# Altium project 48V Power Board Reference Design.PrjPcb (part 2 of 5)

## Sheet TPS4HC120-Q1.SchDoc
size 431 x 279 mm; Date: Not shown in title block; ApprovedBy: Not shown in title block; CheckedBy: Not shown in title block; Author: Not shown in title block; CompanyName: Not shown in title block; Engineer: Not shown in title block; Organization: Not shown in title block; Address1: Not shown in title block; Address2: Not shown in title block; Address3: Not shown in title block; Address4: Not shown in title block; DocumentNumber: 12; Revision: Use project parameter SCH_Rev; SheetNumber: 9; SheetTotal: 15; PageSetup: Record=PageOptions¦CenterHorizontal=True¦CenterVertical=True¦PrintScale=1.00¦XCorrection=1.00¦YCorrection=1.00¦PrintKind=0¦BorderSize=5000000¦LeftOffset=0¦BottomOffset=0¦Orientation=2¦PaperLength=1000¦PaperWidth=1000¦Scale=100¦PaperSource=15¦PrintQuality=600¦MediaType=1¦DitherType=10¦PaperKind=Letter¦PrintScaleMode=1
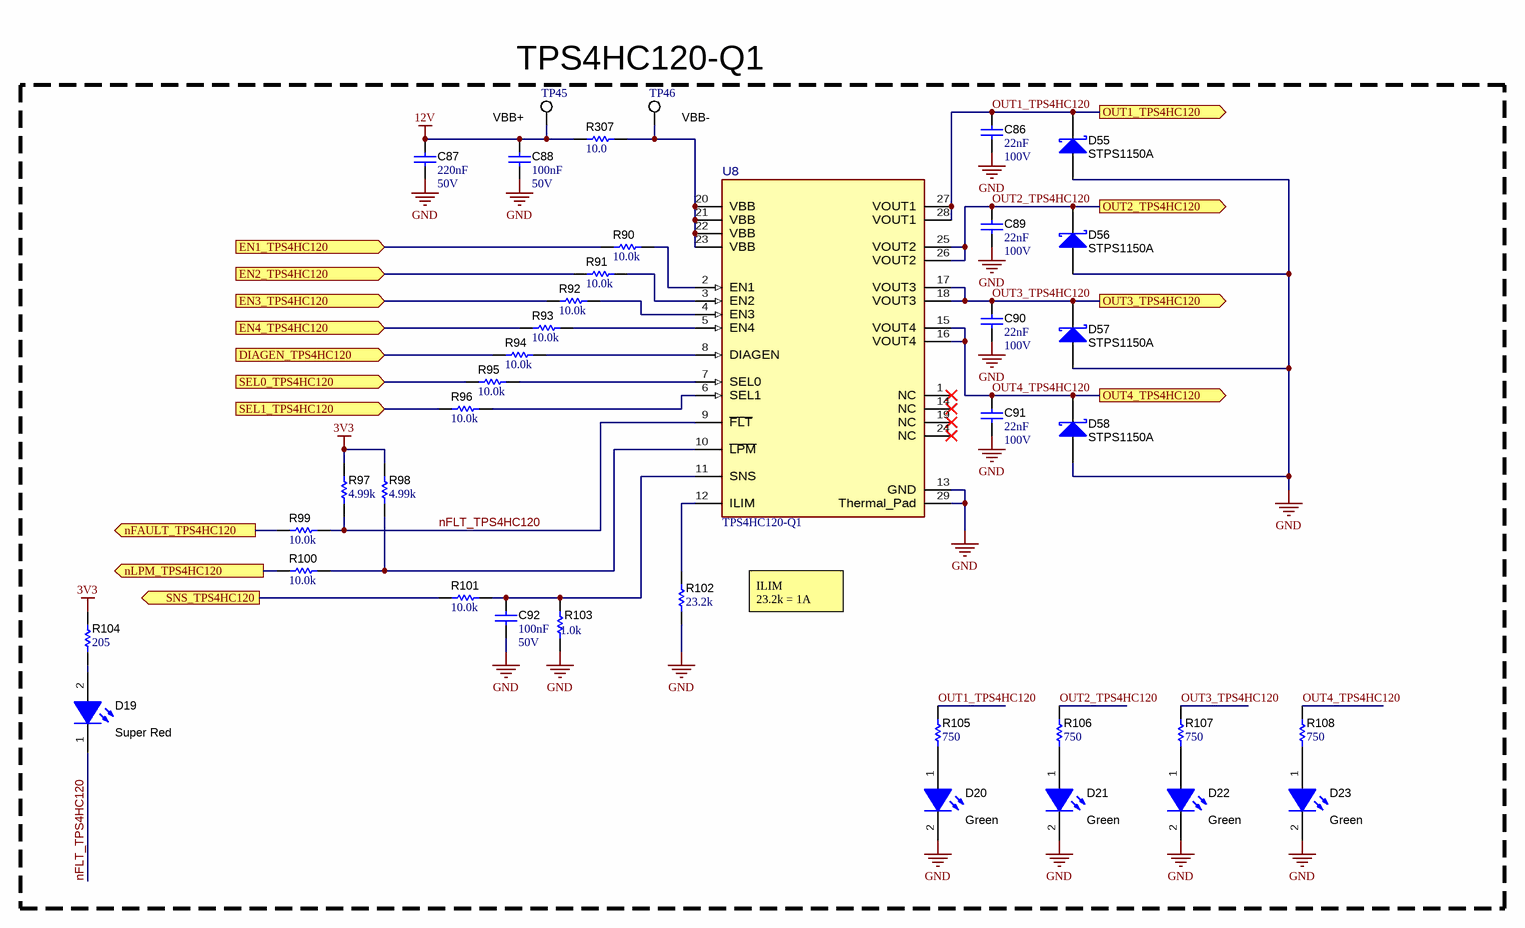
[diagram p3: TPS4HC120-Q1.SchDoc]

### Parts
C86  Cap_F: 22nF  VDC_V: 100V  [0603]  (hidden comment: CGA3E2X7R2A223K080AA)
C87  Cap_F: 220nF  VDC_V: 50V  [0603]  (hidden comment: GCJ188R71H224KA01D)
C88  Cap_F: 100nF  VDC_V: 50V  [0603]  (hidden comment: 06035C104KAZ2A)
C89  Cap_F: 22nF  VDC_V: 100V  [0603]  (hidden comment: CGA3E2X7R2A223K080AA)
C90  Cap_F: 22nF  VDC_V: 100V  [0603]  (hidden comment: CGA3E2X7R2A223K080AA)
C91  Cap_F: 22nF  VDC_V: 100V  [0603]  (hidden comment: CGA3E2X7R2A223K080AA)
C92  Cap_F: 100nF  VDC_V: 50V  [0603]  (hidden comment: 06035C104KAZ2A)
D19  value Super Red  [WL-SMCW_RED]  (hidden comment: 150060SS75000)
D20  value Green  [LTST-C191_Green]  (hidden comment: LTST-C191KGKT)
D21  value Green  [LTST-C191_Green]  (hidden comment: LTST-C191KGKT)
D22  value Green  [LTST-C191_Green]  (hidden comment: LTST-C191KGKT)
D23  value Green  [LTST-C191_Green]  (hidden comment: LTST-C191KGKT)
D55  STPS1150A  [SMA]
D56  STPS1150A  [SMA]
D57  STPS1150A  [SMA]
D58  STPS1150A  [SMA]
R90  ValueDisplayed: 10.0k  [0603]  (hidden comment: RMCF0603FT10K0)
R91  ValueDisplayed: 10.0k  [0603]  (hidden comment: RMCF0603FT10K0)
R92  ValueDisplayed: 10.0k  [0603]  (hidden comment: RMCF0603FT10K0)
R93  ValueDisplayed: 10.0k  [0603]  (hidden comment: RMCF0603FT10K0)
R94  ValueDisplayed: 10.0k  [0603]  (hidden comment: RMCF0603FT10K0)
R95  ValueDisplayed: 10.0k  [0603]  (hidden comment: RMCF0603FT10K0)
R96  ValueDisplayed: 10.0k  [0603]  (hidden comment: RMCF0603FT10K0)
R97  ValueDisplayed: 4.99k  [0603]  (hidden comment: CRCW06034K99FKEA)
R98  ValueDisplayed: 4.99k  [0603]  (hidden comment: CRCW06034K99FKEA)
R99  ValueDisplayed: 10.0k  [0603]  (hidden comment: RMCF0603FT10K0)
R100  ValueDisplayed: 10.0k  [0603]  (hidden comment: RMCF0603FT10K0)
R101  ValueDisplayed: 10.0k  [0603]  (hidden comment: RMCF0603FT10K0)
R102  ValueDisplayed: 23.2k  [0603]  (hidden comment: CRCW060323K2FKEA)
R103  ValueDisplayed: 1.0k  [0603]  (hidden comment: ESR03EZPJ102)
R104  ValueDisplayed: 205  [0603]  (hidden comment: RC0603FR-07205RL)
R105  ValueDisplayed: 750  [0603]  (hidden comment: RC0603FR-07750RL)
R106  ValueDisplayed: 750  [0603]  (hidden comment: RC0603FR-07750RL)
R107  ValueDisplayed: 750  [0603]  (hidden comment: RC0603FR-07750RL)
R108  ValueDisplayed: 750  [0603]  (hidden comment: RC0603FR-07750RL)
R307  ValueDisplayed: 10.0  [0603]  (hidden comment: RC0603FR-0710RL)
TP45  VBB+  [Keystone5012]
TP46  VBB-  [Keystone5012]
U8  TPS4HC120-Q1  [DGQ0028A-MFG]

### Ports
DIAGEN_TPS4HC120 (in), EN1_TPS4HC120 (in), EN2_TPS4HC120 (in), EN3_TPS4HC120 (in), EN4_TPS4HC120 (in), nFAULT_TPS4HC120 (out), nLPM_TPS4HC120 (out), OUT1_TPS4HC120 (out), OUT2_TPS4HC120 (out), OUT3_TPS4HC120 (out), OUT4_TPS4HC120 (out), SEL0_TPS4HC120 (in), SEL1_TPS4HC120 (in), SNS_TPS4HC120 (out)

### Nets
3V3: R97.2 R98.2 R104.2
12V: C87.1 C88.1 R307.1 TP45.1
GND: C86.2 C87.2 C88.2 C89.2 C90.2 C91.2 C92.2 D20.2(K) D21.2(K) D22.2(K) D23.2(K) D55.2(A) D56.2(A) D57.2(A) D58.2(A) R102.1 R103.1 U8.13(GND) U8.29(Thermal_Pad)
DIAGEN_TPS4HC120: R94.2 ; port DIAGEN_TPS4HC120
EN1_TPS4HC120: R90.2 ; port EN1_TPS4HC120
EN2_TPS4HC120: R91.2 ; port EN2_TPS4HC120
EN3_TPS4HC120: R92.2 ; port EN3_TPS4HC120
EN4_TPS4HC120: R93.2 ; port EN4_TPS4HC120
nFAULT_TPS4HC120: R99.2 ; port nFAULT_TPS4HC120
nFLT_TPS4HC120: D19.1(K) R97.1 R99.1 U8.9(~{FLT})  [project net nFLT_TPS4HC120_9]
nLPM_TPS4HC120: R100.2 ; port nLPM_TPS4HC120
OUT1_TPS4HC120: C86.1 D55.1(K) R105.2 U8.27(VOUT1) U8.28(VOUT1) ; port OUT1_TPS4HC120
OUT2_TPS4HC120: C89.1 D56.1(K) R106.2 U8.25(VOUT2) U8.26(VOUT2) ; port OUT2_TPS4HC120
OUT3_TPS4HC120: C90.1 D57.1(K) R107.2 U8.17(VOUT3) U8.18(VOUT3) ; port OUT3_TPS4HC120
OUT4_TPS4HC120: C91.1 D58.1(K) R108.2 U8.15(VOUT4) U8.16(VOUT4) ; port OUT4_TPS4HC120
SEL0_TPS4HC120: R95.2 ; port SEL0_TPS4HC120
SEL1_TPS4HC120: R96.2 ; port SEL1_TPS4HC120
SNS_TPS4HC120: R101.2 ; port SNS_TPS4HC120
NetC92_1: C92.1 R101.1 R103.2 U8.11(SNS)
NetD19_2: D19.2(A) R104.1
NetD20_1: D20.1(A) R105.1
NetD21_1: D21.1(A) R106.1
NetD22_1: D22.1(A) R107.1
NetD23_1: D23.1(A) R108.1
NetR90_1: R90.1 U8.2(EN1)
NetR91_1: R91.1 U8.3(EN2)
NetR92_1: R92.1 U8.4(EN3)
NetR93_1: R93.1 U8.5(EN4)
NetR94_1: R94.1 U8.8(DIAGEN)
NetR95_1: R95.1 U8.7(SEL0)
NetR96_1: R96.1 U8.6(SEL1)
NetR98_1: R98.1 R100.1 U8.10(~{LPM})
NetR102_2: R102.2 U8.12(ILIM)
NetR307_2: R307.2 TP46.1 U8.20(VBB) U8.21(VBB) U8.22(VBB) U8.23(VBB)

Not connected (* = marked no-connect by the designer): U8 1(NC)* 14(NC)* 19(NC)* 24(NC)*

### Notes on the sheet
- TPS4HC120-Q1
- ILIM                      23.2k = 1A

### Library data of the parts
C86 C89-C91 = CMP-0007086-4: CAP, CERM, 0.022 uF, 100 V, +/- 10%, X7R, AEC-Q200 Grade 1, 0603; Manufacturer: TDK; TaMin_C: -55°C; ESR_ohm: 83.542m; Polarized: N; SizeAreaWB_mm2: 4.68; Value1: 0.083542 ohm; U/M: EA; TaMax_C: 125°C; SizeZ_mm: 1; SizeX_mm: 1.6; SizeY_mm: 0.8; SizeArea_mm2: 1.28; AEC Qualified: Y; IRMS_A: 609.312mA; AEC Category: Q200
C87 = CMP-0079579-1: CAP, CERM, 0.22 µF, 50 V,+/- 10%, X7R, AEC-Q200 Grade 1, 0603; Manufacturer: MuRata; SizeAreaWB_mm2: 4.68; SizeArea_mm2: 1.28; AEC Qualified: Y; AEC Category: Q200; Value: 0.22uF; TaMax_C: 125°C; SizeZ_mm: 1; Polarized: N; TaMin_C: -55°C; SizeY_mm: 0.8; U/M: EA; SizeX_mm: 1.6; ValueDisplayed: 0.22µF
C88 C92 = CMP-0079095-1: CAP, CERM, 0.1 µF, 50 V,+/- 10%, X7R, AEC-Q200 Grade 1, 0603; Manufacturer: AVX; SizeAreaWB_mm2: 4.68; SizeArea_mm2: 1.28; AEC Qualified: Y; AEC Category: Q200; Value: 0.1uF; TaMax_C: 125°C; SizeZ_mm: 1; Polarized: N; TaMin_C: -55°C; SizeY_mm: 0.8; U/M: EA; SizeX_mm: 1.6; ValueDisplayed: 0.1µF
D19 = CMP-0002893-1: LED, Super Red, SMD; Manufacturer: Wurth Elektronik; Io_A: 20mA; Value1: W; U/M: EA; Vf_V: 1.9V; Type: AlInGaP
D20-D23 = CMP-0078478-1: LED, Green, SMD; Manufacturer: Lite-On; Io_A: 30mA; Power_TotalModule: 75mW; Green_Lifecycle: Not Set; Vr_V: 5V; Tjmax_C: 85°C; Green_REACh: Incomplete; Value1: 0.075W; Angle: 130; Ir_A: 10µA; Vf_V: 2V; Type: AlInGaP
D55-D58 = CMP-0028752-1: Diode, Schottky, 150 V, 1 A, SMA; Manufacturer: STMicroelectronics; Io_A: 1A; Green_Lifecycle: Not Set; SizeAreaWB_mm2: 37.3428; Vr_V: 150V; Green_REACh: Incomplete; TJmax_C: 175°C; U/M: EA; Value: 150V; SizeZ_mm: 2.87; SizeX_mm: 5.59; SizeY_mm: 2.92; Vf_V: 780mV; Value2: 0.78V; SizeArea_mm2: 16.3228; AEC Qualified: N; AEC Category: Q101; RJC_CperW: 30
R90-R96 R99-R101 = CMP-0023341-2: RES, 10.0 k, 1%, 0.1 W, AEC-Q200 Grade 0, 0603; Manufacturer: Stackpole Electronics Inc; Power_W: 100mW; TempCo: 100 ppm/C; Value_Code: 10k0; U/M: EA; Value: 10.0k; EIA_Code: E96; Res_ohm: 10k; SizeX_mm: 1.6; SizeY_mm: 0.8; SizeZ_mm: 1; Value2: 0.1W; SizeArea_mm2: 1.28; AEC Qualified: Y; VDC_V: 75V; AEC Grade: 0; AEC Category: Q200
R97 R98 = CMP-0022458-4: RES, 4.99 k, 1%, 0.1 W, AEC-Q200 Grade 0, 0603; Manufacturer: Vishay-Dale; Power_W: 100mW; TempCo: 100 ppm/C; Value_Code: 4k99; Value: 4.99k; EIA_Code: E96; SizeX_mm: 1.6; SizeY_mm: 0.8; SizeZ_mm: 1; Value2: 0.1W; SizeArea_mm2: 1.28; AEC Qualified: Y; VDC_V: 75V; AEC Category: Q200; AEC Grade: 0
R102 = CMP-0022228-4: RES, 23.2 k, 1%, 0.1 W, AEC-Q200 Grade 0, 0603; Manufacturer: Vishay-Dale; Power_W: 100mW; TempCo: 100 ppm/C; Value_Code: 23k2; Value: 23.2k; EIA_Code: E96; SizeX_mm: 1.6; SizeY_mm: 0.8; SizeZ_mm: 1; Value2: 0.1W; SizeArea_mm2: 1.28; AEC Qualified: Y; VDC_V: 75V; AEC Category: Q200; AEC Grade: 0
R103 = CMP-0084244-1: RES, 1.0 k, 5%, 0.25 W, AEC-Q200 Grade 0, 0603; Manufacturer: Rohm; Power_W: 250mW; TempCo: 200 ppm/C; SizeAreaWB_mm2: 4.68; Value_Code: 1k00; Value: 1.0k; EIA_Code: E24; Res_ohm: 1k; SizeX_mm: 1.6; SizeY_mm: 0.8; SizeZ_mm: 1; Value2: 0.25W; SizeArea_mm2: 1.28; AEC Qualified: Y; AEC Grade: 0; AEC Category: Q200
R104 = CMP-0022904-5: RES, 205, 1%, 0.1 W, 0603; Manufacturer: Yageo; Power_W: 100mW; TempCo: 100 ppm/C; Value_Code: 205R; Value: 205; EIA_Code: E96; SizeX_mm: 1.6; SizeY_mm: 0.8; SizeZ_mm: 1; Value2: 0.1W; SizeArea_mm2: 1.28; AEC Qualified: N; VDC_V: 75V; AEC Category: Q200; SizeAreaWB_mm2: 4.68
R105-R108 = CMP-0023266-5: RES, 750, 1%, 0.1 W, 0603; Manufacturer: Yageo; Power_W: 100mW; TempCo: 100 ppm/C; Value_Code: 750R; Value: 750; EIA_Code: E96; SizeX_mm: 1.6; SizeY_mm: 0.8; SizeZ_mm: 1; Value2: 0.1W; SizeArea_mm2: 1.28; AEC Qualified: N; VDC_V: 75V; AEC Category: Q200; SizeAreaWB_mm2: 4.68
R307 = CMP-0022751-4: RES, 10.0, 1%, 0.1 W, 0603; Manufacturer: Yageo; Power_W: 100mW; TempCo: 100 ppm/C; Value_Code: 10R0; Value: 10.0; EIA_Code: E96; Res_ohm: 10; SizeX_mm: 1.6; SizeY_mm: 0.8; SizeZ_mm: 1; Value2: 0.1W; SizeArea_mm2: 1.28; AEC Qualified: N; VDC_V: 75V; AEC Category: Q200; SizeAreaWB_mm2: 4.68
TP45 TP46 = CMP-0055149-1: Test Point, Multipurpose, White, TH; Manufacturer: Keystone; CNHeader: FALSE; Green_Lifecycle: Active; Green_REACh: Passed; ContactFinish: Silver; CT: TRUE
U8 = CMP-0038451-2: 1A, 120-mΩ Quad-Channel Smart High-Side Switch; Manufacturer: Texas Instruments; SizeZ_mm: 1.1mm; AEC Qualified: Yes; AEC Grade: Grade 1; Max Supply Voltage: 18V; Min Supply Voltage: 6V; Nominal Supply Current: 1.3-4.9mA; Number Of Outputs: 4; Standoff Height: 0mm; TaMax_C: +125°C; TaMin_C: -40°C; TJmax_C: +150°C; AEC Category: Q200; CompType: IC

## Sheet TPS1214-Q1.SchDoc
size 431 x 279 mm; Date: Not shown in title block; ApprovedBy: Not shown in title block; CheckedBy: Not shown in title block; Author: Not shown in title block; CompanyName: Not shown in title block; Engineer: Not shown in title block; Organization: Not shown in title block; Address1: Not shown in title block; Address2: Not shown in title block; Address3: Not shown in title block; Address4: Not shown in title block; DocumentNumber: 8; Revision: Use project parameter SCH_Rev; SheetNumber: 7; SheetTotal: 15; PageSetup: Record=PageOptions¦CenterHorizontal=True¦CenterVertical=True¦PrintScale=1.00¦XCorrection=1.00¦YCorrection=1.00¦PrintKind=0¦BorderSize=5000000¦LeftOffset=0¦BottomOffset=0¦Orientation=2¦PaperLength=1000¦PaperWidth=1000¦Scale=100¦PaperSource=15¦PrintQuality=600¦MediaType=1¦DitherType=10¦PaperKind=Letter¦PrintScaleMode=1
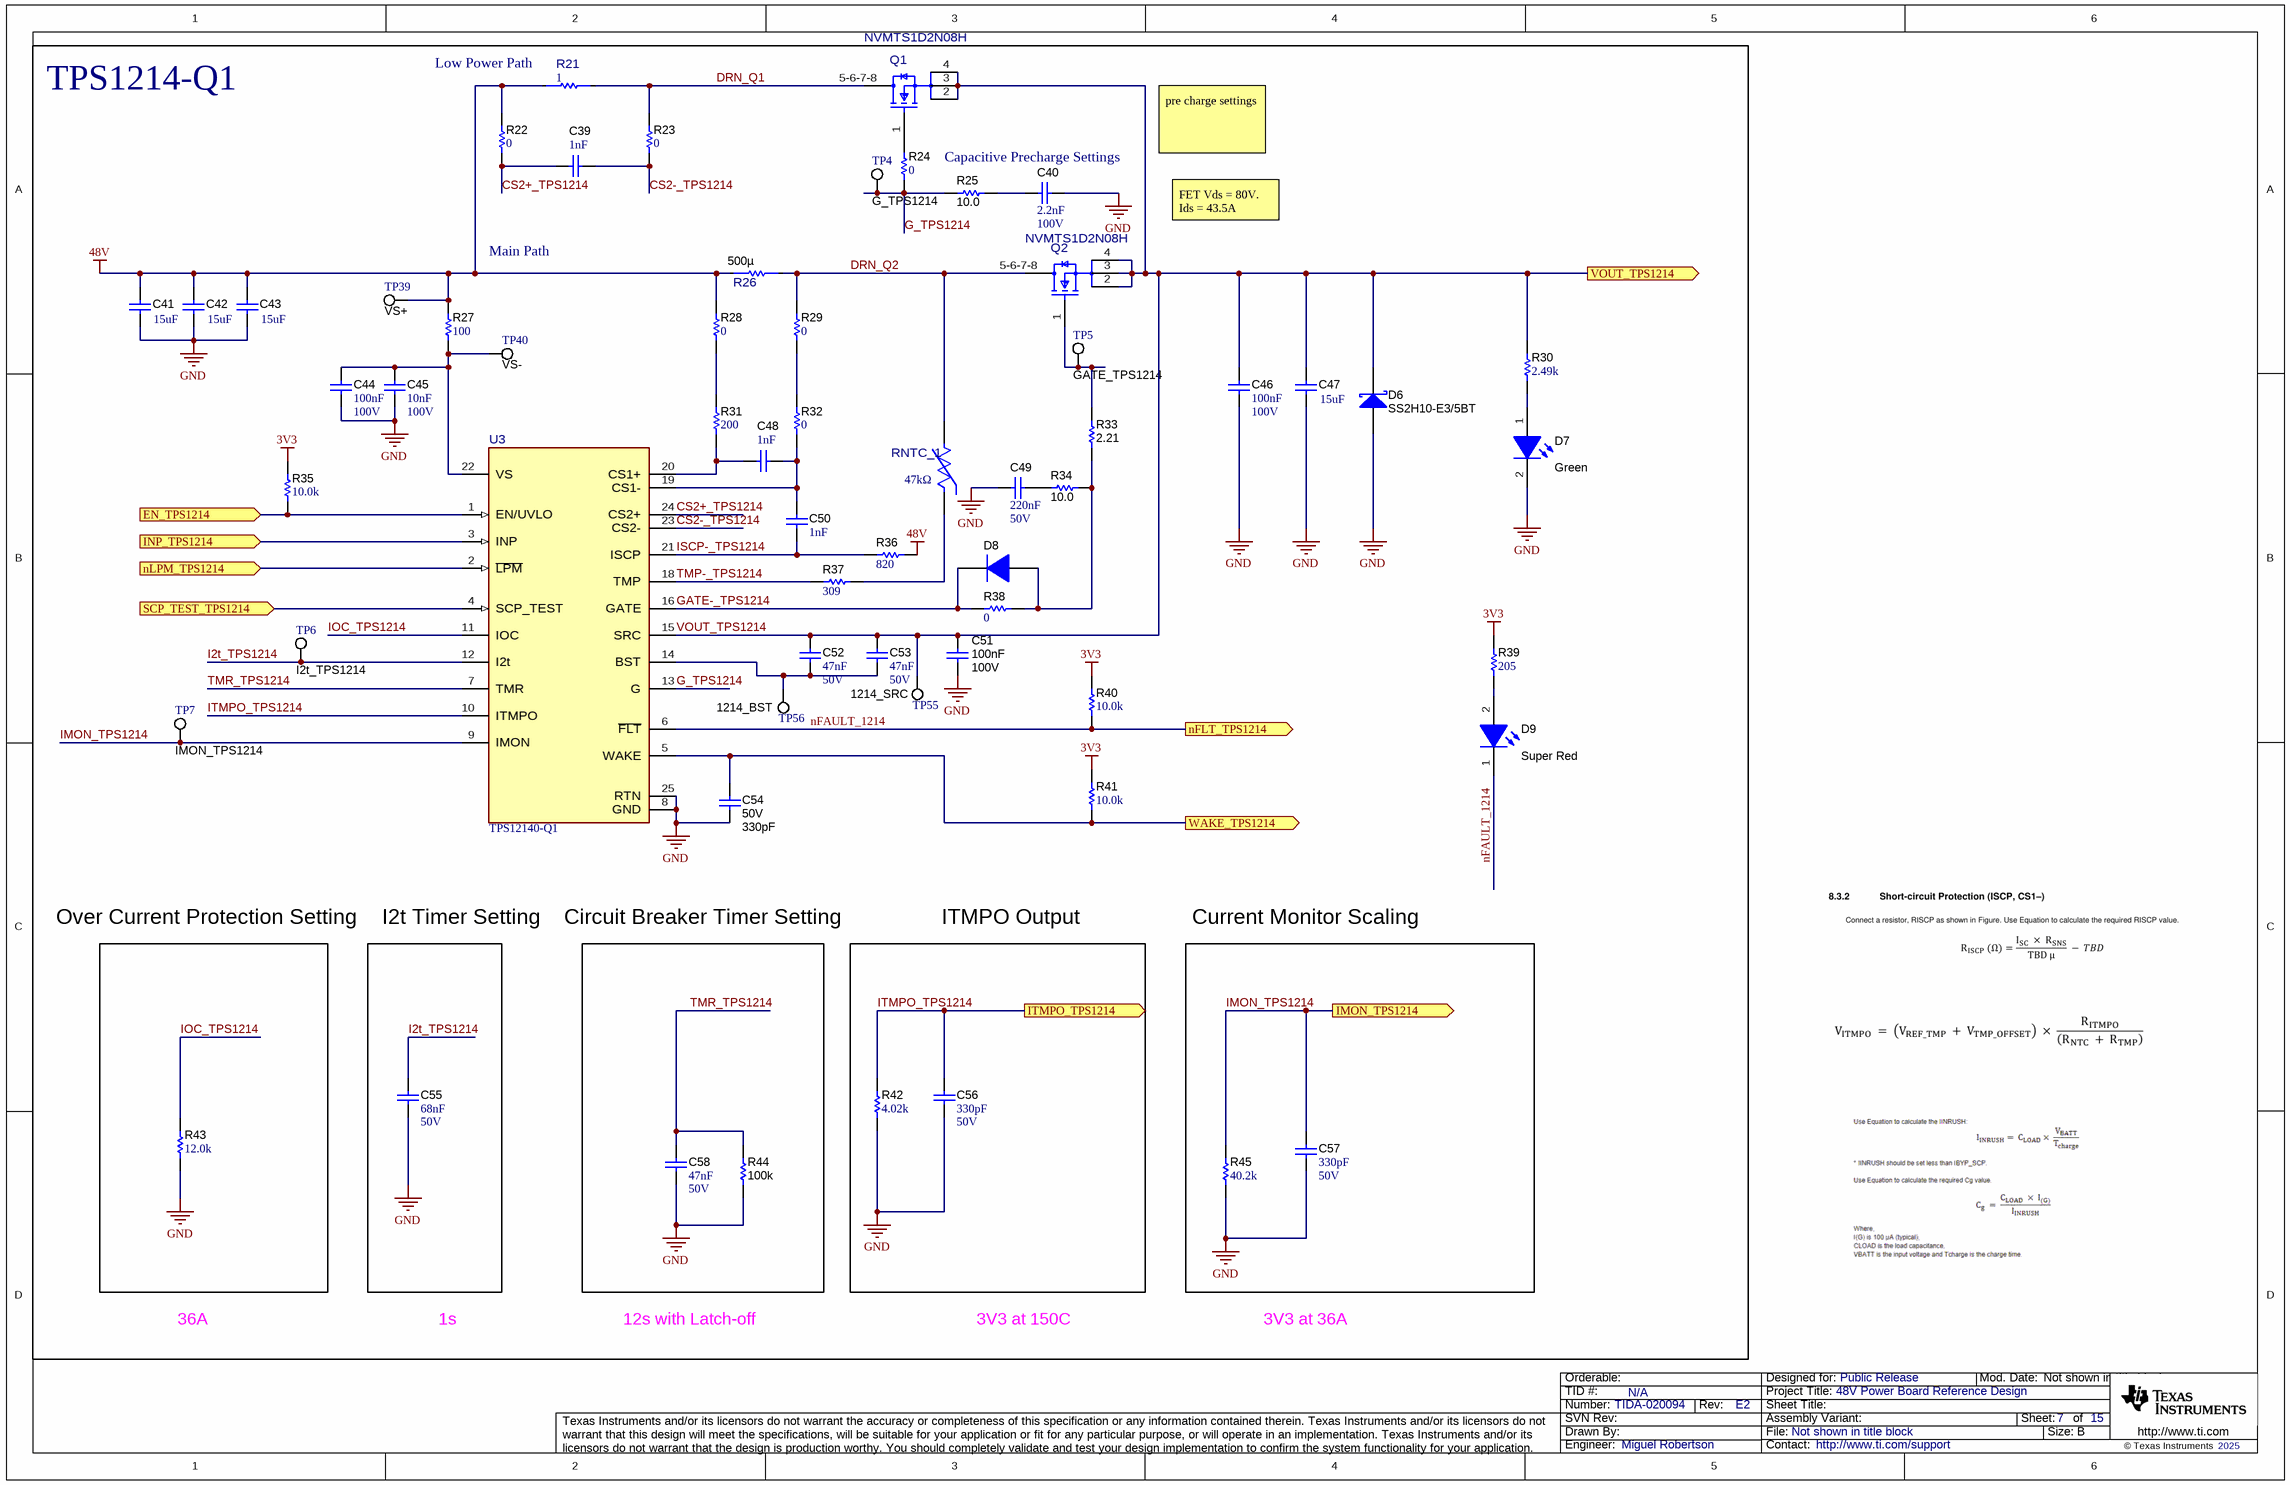
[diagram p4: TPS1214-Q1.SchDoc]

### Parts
C39  Cap_F: 1nF  [0603]  (hidden comment: C0603X102K5RACTU)
C40  Cap_F: 2.2nF  VDC_V: 100V  [0603]  (hidden comment: CGA3E2X7R2A222K080AA)
C41  ValueDisplayed: 15uF  [KCM55W]  (hidden comment: KCM55WR72A156MH01K)
C42  ValueDisplayed: 15uF  [KCM55W]  (hidden comment: KCM55WR72A156MH01K)
C43  ValueDisplayed: 15uF  [KCM55W]  (hidden comment: KCM55WR72A156MH01K)
C44  Cap_F: 100nF  VDC_V: 100V  [0603]  (hidden comment: HMK107B7104KAHT)
C45  Cap_F: 10nF  VDC_V: 100V  [0603]  (hidden comment: CGA3E2X7R2A103K080AA)
C46  Cap_F: 100nF  VDC_V: 100V  [0603]  (hidden comment: HMK107B7104KAHT)
C47  ValueDisplayed: 15uF  [KCM55W]  (hidden comment: KCM55WR72A156MH01K)
C48  Cap_F: 1nF  [0603]  (hidden comment: C0603X102K5RACTU)
C49  Cap_F: 220nF  VDC_V: 50V  [0603]  (hidden comment: RC0603FR-07200RL)
C50  Cap_F: 1nF  [0603]  (hidden comment: C0603X102K5RACTU)
C51  Cap_F: 100nF  VDC_V: 100V  [0805_HV]  (hidden comment: CGA4J2X7R2A104K125AA)
C52  Cap_F: 47nF  VDC_V: 50V  [0603]  (hidden comment: CGA3E2X7R1H473K080AA)
C53  Cap_F: 47nF  VDC_V: 50V  [0603]  (hidden comment: CGA3E2X7R1H473K080AA)
C54  VDC_V: 50V  ValueDisplayed: 330pF  [0402]  (hidden comment: GRM155R71H331KA01D)
C55  Cap_F: 68nF  VDC_V: 50V  [0603]  (hidden comment: CGA3E2X7R1H683K080AA)
C56  Cap_F: 330pF  VDC_V: 50V  [0603]  (hidden comment: C0603C331K5RACTU)
C57  Cap_F: 330pF  VDC_V: 50V  [0603]  (hidden comment: C0603C331K5RACTU)
C58  Cap_F: 47nF  VDC_V: 50V  [0603]  (hidden comment: CGA3E2X7R1H473K080AA)
D6  SS2H10-E3/5BT  [SMB]
D7  value Green  [LTST-C191_Green]  (hidden comment: LTST-C191KGKT)
D8  1N4148W-TP  [SOD-123]  (value not drawn)
D9  value Super Red  [WL-SMCW_RED]  (hidden comment: 150060SS75000)
Q1  NVMTS1D2N08H  [FP-NVMTS1D2N08H_DFNW8-MFG]
Q2  NVMTS1D2N08H  [FP-NVMTS1D2N08H_DFNW8-MFG]
R21  value 1  [FP-VMP-1R00-1.0-U_2010-MFG]  (hidden comment: VMP-1R00-1.0-U)
R22  ValueDisplayed: 0  [0603]  (hidden comment: CRCW06030000Z0EA)
R23  ValueDisplayed: 0  [0603]  (hidden comment: CRCW06030000Z0EA)
R24  ValueDisplayed: 0  [0603]  (hidden comment: CRCW06030000Z0EA)
R25  ValueDisplayed: 10.0  [0805_HV]  (hidden comment: RC0805FR-0710RL)
R26  Res_ohm: 500µ  [FP-WSL3921L5000FEA_3921-MFG]  (hidden comment: WSL3921L5000FEA)
R27  ValueDisplayed: 100  [0603]  (hidden comment: ERJ-3EKF1000V)
R28  ValueDisplayed: 0  [0603]  (hidden comment: CRCW06030000Z0EA)
R29  ValueDisplayed: 0  [0603]  (hidden comment: CRCW06030000Z0EA)
R30  ValueDisplayed: 2.49k  [0603]  (hidden comment: RC0603FR-072K49L)
R31  ValueDisplayed: 200  [0603]  (hidden comment: RC0603FR-07200RL)
R32  ValueDisplayed: 0  [0603]  (hidden comment: CRCW06030000Z0EA)
R33  ValueDisplayed: 2.21  [0603]  (hidden comment: RC0603FR-072R21L)
R34  ValueDisplayed: 10.0  [0805_HV]  (hidden comment: CGA4J2X7R2A104K125AA)
R35  ValueDisplayed: 10.0k  [0603]  (hidden comment: RNCF0603TKY10K0)
R36  ValueDisplayed: 820  [0603]  (hidden comment: RC0603FR-07820RL)
R37  ValueDisplayed: 309  [0603]  (hidden comment: RC0603FR-07309RL)
R38  ValueDisplayed: 0  [0603]  (hidden comment: CRCW06030000Z0EA)
R39  ValueDisplayed: 205  [0603]  (hidden comment: RC0603FR-07205RL)
R40  ValueDisplayed: 10.0k  [TNPW0603]  (hidden comment: TNPW060310K0BEEA)
R41  ValueDisplayed: 10.0k  [TNPW0603]  (hidden comment: TNPW060310K0BEEA)
R42  ValueDisplayed: 4.02k  [0603]  (hidden comment: CRCW06034K02FKEA)
R43  ValueDisplayed: 12.0k  [0603]  (hidden comment: RC0603FR-0712KL)
R44  ValueDisplayed: 100k  [0603]  (hidden comment: CRCW0603100KFKEA)
R45  ValueDisplayed: 40.2k  [0603]  (hidden comment: RC0603FR-0740K2L)
RNTC_1  value 47kΩ  [FP-NCU18WB473J6SRB_0603-MFG]  (hidden comment: NCU18WB473J6SRB)
TP4  G_TPS1214  [Keystone5012]
TP5  GATE_TPS1214  [Keystone5012]
TP6  I2t_TPS1214  [Keystone5012]
TP7  IMON_TPS1214  [Keystone5012]
TP39  VS+  [Keystone5012]
TP40  VS-  [Keystone5012]
TP55  1214_SRC  [Keystone5012]
TP56  1214_BST  [Keystone5012]
U3  TPS12140-Q1  [RGE0023A-MFG]

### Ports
EN_TPS1214 (in), IMON_TPS1214 (out), INP_TPS1214 (in), ITMPO_TPS1214 (out), nFLT_TPS1214 (out), nLPM_TPS1214 (in), SCP_TEST_TPS1214 (in), VOUT_TPS1214 (out), WAKE_TPS1214 (out)

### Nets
3V3: R35.2 R39.2 R40.2 R41.2
48V: C41.1 C42.1 C43.1 R21.1 R22.2 R26.1 R27.2 R28.2 R36.2 TP39.1
GND: C40.1 C41.2 C42.2 C43.2 C44.2 C45.2 C46.2 C47.2 C49.1 C51.2 C54.2 C55.2 C56.2 C57.2 C58.2 D6.2(A) D7.2(K) R42.1 R43.1 R44.1 R45.1 U3.8(GND) U3.25(RTN)
CS2+_TPS1214: C39.2 R22.1 U3.24(CS2+)  [project net CS2+_TPS1214_7]
CS2-_TPS1214: C39.1 R23.1 U3.23(CS2-)  [project net CS2-_TPS1214_7]
DRN_Q1: Q1.5-6-7-8(D) R21.2 R23.2  [project net DRN_Q1_7]
DRN_Q2: Q2.5-6-7-8(D) R26.2 R29.2 RNTC_1.2  [project net DRN_Q2_7]
EN_TPS1214: R35.1 U3.1(EN/UVLO) ; port EN_TPS1214
G_TPS1214: R24.1 R25.2 TP4.1 U3.13(G)  [project net G_TPS1214_7]
GATE-_TPS1214: D8.1(K) R38.2 U3.16(GATE)  [project net GATE-_TPS1214_7]
I2t_TPS1214: C55.1 TP6.1 U3.12(I2t)  [project net I2t_TPS1214_7]
IMON_TPS1214: C57.1 R45.2 TP7.1 U3.9(IMON) ; port IMON_TPS1214
INP_TPS1214: U3.3(INP) ; port INP_TPS1214
IOC_TPS1214: R43.2 U3.11(IOC)  [project net IOC_TPS1214_7]
ISCP-_TPS1214: C50.2 R36.1 U3.21(ISCP)  [project net ISCP-_TPS1214_7]
ITMPO_TPS1214: C56.1 R42.2 U3.10(ITMPO) ; port ITMPO_TPS1214
nFAULT_1214: D9.1(K) R40.1 U3.6(~{FLT}) ; port nFLT_TPS1214
nLPM_TPS1214: U3.2(~{LPM}) ; port nLPM_TPS1214
SCP_TEST_TPS1214: U3.4(SCP_TEST) ; port SCP_TEST_TPS1214
TMP-_TPS1214: R37.1 U3.18(TMP)  [project net TMP-_TPS1214_7]
TMR_TPS1214: C58.1 R44.2 U3.7(TMR)  [project net TMR_TPS1214_7]
VOUT_TPS1214: C46.1 C47.1 C51.1 C52.1 C53.1 D6.1(K) Q1.2(S) Q1.3(S) Q1.4(S) Q2.2(S) Q2.3(S) Q2.4(S) R30.2 TP55.1 U3.15(SRC) ; port VOUT_TPS1214
WAKE_TPS1214: C54.1 R41.1 U3.5(WAKE) ; port WAKE_TPS1214
NetC40_2: C40.2 R25.1
NetC44_1: C44.1 C45.1 R27.1 TP40.1 U3.22(VS)
NetC48_1: C48.1 C50.1 R32.1 U3.19(CS1-)
NetC48_2: C48.2 R31.1 U3.20(CS1+)
NetC49_2: C49.2 R34.1
NetC52_2: C52.2 C53.2 TP56.1 U3.14(BST)
NetD7_1: D7.1(A) R30.1
NetD8_2: D8.2(A) R33.1 R34.2 R38.1
NetD9_2: D9.2(A) R39.1
NetQ1_1: Q1.1(G) R24.2
NetQ2_1: Q2.1(G) R33.2 TP5.1
NetR28_1: R28.1 R31.2
NetR29_1: R29.1 R32.2
NetR37_2: R37.2 RNTC_1.1

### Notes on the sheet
- TPS1214-Q1
- (near R21) Low Power Path
- Capacitive Precharge Settings
- pre charge settings
- FET Vds = 80V. Ids = 43.5A
- Main Path
- Over Current Protection Setting
- I2t Timer Setting
- Circuit Breaker Timer Setting
- ITMPO Output
- Current Monitor Scaling
- 36A
- 1s
- 12s with Latch-off
- 3V3 at 150C
- 3V3 at 36A

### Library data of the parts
C39 C48 C50 = CMP-0006976-5: CAP, CERM, 1000 pF, 50 V, +/- 10%, X7R, 0603; Manufacturer: Kemet; TaMin_C: -55°C; Polarized: N; SizeAreaWB_mm2: 4.68; Value1: Unknown; U/M: EA; Value: 1000pF; TaMax_C: 125°C; SizeZ_mm: 1; SizeX_mm: 1.6; SizeY_mm: 0.8; Value2: 50V; SizeArea_mm2: 1.28; AEC Category: Q200
C40 = CMP-0007085-4: CAP, CERM, 2200 pF, 100 V, +/- 10%, X7R, AEC-Q200 Grade 1, 0603; Manufacturer: TDK; TaMin_C: -55°C; ESR_ohm: 0.9239; Polarized: N; SizeAreaWB_mm2: 4.68; Value1: 0.923948 ohm; U/M: EA; Value: 2200pF; TaMax_C: 125°C; SizeZ_mm: 1; SizeX_mm: 1.6; SizeY_mm: 0.8; SizeArea_mm2: 1.28; AEC Qualified: Y; IRMS_A: 295.638mA; AEC Category: Q200
C41-C43 C47 = CMP-0009477-2: CAP, CERM, 15 uF, 100 V, +/- 20%, X7R, Stacked 2220; Manufacturer: MuRata; TaMin_C: -55°C; Polarized: N; SizeAreaWB_mm2: 59.13; Value1: Unknown; U/M: EA; Value: 15uF; TaMax_C: 125°C; SizeZ_mm: 6.7; SizeX_mm: 6.1; SizeY_mm: 5.3; Cap_Case: 2220; Value2: 100V; SizeArea_mm2: 32.33; Cap_F: 15µF; AEC Category: Q200
C44 C46 = CMP-0081011-1: CAP, CERM, 0.1 µF, 100 V,+/- 10%, X7R, AEC-Q200 Grade 1, 0603; Manufacturer: Taiyo Yuden; SizeAreaWB_mm2: 4.68; SizeArea_mm2: 1.28; AEC Qualified: Y; AEC Category: Q200; Value: 0.1uF; TaMax_C: 125°C; SizeZ_mm: 1; Polarized: N; TaMin_C: -55°C; SizeY_mm: 0.8; U/M: EA; SizeX_mm: 1.6; ValueDisplayed: 0.1µF
C45 = CMP-0007082-4: CAP, CERM, 0.01 uF, 100 V, +/- 10%, X7R, AEC-Q200 Grade 1, 0603; Manufacturer: TDK; TaMin_C: -55°C; ESR_ohm: 0.2354; Polarized: N; SizeAreaWB_mm2: 4.68; Value1: 0.235428 ohm; U/M: EA; Value: 0.01uF; TaMax_C: 125°C; SizeZ_mm: 1; SizeX_mm: 1.6; SizeY_mm: 0.8; SizeArea_mm2: 1.28; AEC Qualified: Y; IRMS_A: 396.995mA; AEC Category: Q200
C49 = CMP-0007094-5: CAP, CERM, 0.22 uF, 50 V, +/- 10%, X7R, AEC-Q200 Grade 1, 0603; Manufacturer: TDK; PartNumber: CGA3E3X7R1H224K080AB; TaMin_C: -55°C; ESR_ohm: 21.699m; Polarized: N; SizeAreaWB_mm2: 4.68; Value1: 0.021699 ohm; U/M: EA; Value: 0.22uF; TaMax_C: 125°C; SizeZ_mm: 1; SizeX_mm: 1.6; SizeY_mm: 0.8; SizeArea_mm2: 1.28; AEC Qualified: Y; IRMS_A: 1.125A; AEC Category: Q200
C51 = CMP-0007969-2: CAP, CERM, 0.1 uF, 100 V, +/- 10%, X7R, AEC-Q200 Grade 1, 0805; Manufacturer: TDK; TaMin_C: -55°C; ESR_ohm: 0.020726; Polarized: N; SizeAreaWB_mm2: 6.75; Value1: 0.020726 ohm; U/M: EA; Value: 0.1uF; TaMax_C: 125°C; SizeZ_mm: 1.45; SizeX_mm: 2; SizeY_mm: 1.25; Cap_Case: 0805; SizeArea_mm2: 2.5; AEC Qualified: Y; IRMS_A: 1.456A; AEC Grade: 1; AEC Category: Q200
C52 C53 C58 = CMP-0007079-4: CAP, CERM, 0.047 uF, 50 V, +/- 10%, X7R, AEC-Q200 Grade 1, 0603; Manufacturer: TDK; TaMin_C: -55°C; ESR_ohm: 49.007m; Polarized: N; SizeAreaWB_mm2: 4.68; Value1: 0.049007 ohm; U/M: EA; TaMax_C: 125°C; SizeZ_mm: 1; SizeX_mm: 1.6; SizeY_mm: 0.8; SizeArea_mm2: 1.28; AEC Qualified: Y; IRMS_A: 767.528mA; AEC Category: Q200
C54 = CMP-0006687-2: CAP, CERM, 330 pF, 50 V, +/- 10%, X7R, 0402; Manufacturer: MuRata; TaMin_C: -55°C; Polarized: N; SizeAreaWB_mm2: 3; Value1: Unknown; U/M: EA; Value: 330pF; TaMax_C: 125°C; SizeZ_mm: 0.6; SizeX_mm: 1; SizeY_mm: 0.5; AEC Category: Q200
C55 = CMP-0007080-5: CAP, CERM, 0.068 uF, 50 V, +/- 10%, X7R, AEC-Q200 Grade 1, 0603; Manufacturer: TDK; TaMin_C: -55°C; ESR_ohm: 35.979m; Polarized: N; SizeAreaWB_mm2: 4.68; Value1: 0.035979 ohm; U/M: EA; TaMax_C: 125°C; SizeZ_mm: 1; SizeX_mm: 1.6; SizeY_mm: 0.8; SizeArea_mm2: 1.28; AEC Qualified: Y; IRMS_A: 886.483mA; AEC Category: Q200
C56 C57 = CMP-0006921-4: CAP, CERM, 330 pF, 50 V, +/- 10%, X7R, 0603; Manufacturer: Kemet; TaMin_C: -55°C; Polarized: N; SizeAreaWB_mm2: 4.68; Value1: Unknown; U/M: EA; Value: 330pF; TaMax_C: 125°C; SizeZ_mm: 1; SizeX_mm: 1.6; SizeY_mm: 0.8; SizeArea_mm2: 1.28; AEC Category: Q200
D6 = CMP-0028987-2: Diode, Schottky, 100 V, 2 A, SMB; Manufacturer: Vishay-Semiconductor; Vf_V: 790mV; AEC Qualified: N; SizeArea_mm2: 21.336; Value: 100V; SizeX_mm: 5.6; Value1: 2A; Value2: 0.79V; SizeZ_mm: 2.6; SizeAreaWB_mm2: 44.156; AEC Category: Q101; TJmax_C: 175°C; SizeY_mm: 3.81
D7 = CMP-0078478-1: as D20-D23 on sheet TPS4HC120-Q1
D8 = CMP-0076974-1: Diode, Switching, 100 V, 0.15 A, SOD-123; Manufacturer: Micro Commercial Components; SizeAreaWB_mm2: 13.095; Vr_V: 100V; SizeArea_mm2: 6.545; TJmax_C: 150°C; AEC Category: Q101; Value: 100V; SizeZ_mm: 1.35; Green_REACh: Incomplete; Io_A: 150mA; Vf_V: 1.25V; SizeY_mm: 1.7; Green_Lifecycle: Not Set; U/M: EA; Value1: 0.15A; SizeX_mm: 3.85
D9 = CMP-0002893-1: as D19 on sheet TPS4HC120-Q1
Q1 Q2 = CMP-0088066-1: N-Channel Power MOSFET 80V 3374A 1.1mOhm 8-Pin DFNW Surface Mount T/R; Manufacturer: ON Semiconductor; IdsMax_A: 43.5A; Vgs_V: 20V; AEC Qualified: Yes; ChMode: False; QgTyp_nC: 147nC @ 10V; SizeZ_mm: 1.2mm; Rdson45_ohm: 930µ
R21 = CMP-0098465-1: 1 Ohms ±1% 3W Chip Resistor 2010 (5025 Metric) Automotive AEC-Q200, Current Sense, Moisture Resistant, Pulse Withstanding; Manufacturer: Isabellenhuette; AEC Grade: Grade 0; AEC Qualified: Yes; SizeZ_mm: 0.55mm; TempCo: 20ppm/°C
R22-R24 R28 R29 R32 R38 = CMP-0025697-4: RES, 0, 5%, 0.1 W, AEC-Q200 Grade 0, 0603; Manufacturer: Vishay-Dale; Power_W: 100mW; TempCo: 200 ppm/C; Value_Code: 0000; Value: 0; EIA_Code: E24; SizeX_mm: 1.6; SizeY_mm: 0.8; SizeZ_mm: 1; Value2: 0.1W; SizeArea_mm2: 1.28; CompType: Resistor; AEC Qualified: Y; VDC_V: 75V; AEC Category: Q200
R25 = CMP-0021863-2: RES, 10.0, 1%, 0.125 W, 0805; Manufacturer: Yageo America; Power_W: 125mW; TempCo: 200 ppm/C; Value_Code: 10R0; U/M: EA; Value: 10.0; EIA_Code: E96; Res_ohm: 10; SizeX_mm: 2; SizeY_mm: 1.25; SizeZ_mm: 1.45; Value2: 0.125W; SizeArea_mm2: 2.5; VDC_V: 150V; AEC Category: Q200
R26 = CMP-0092921-1: Res Metal Strip 3921 0.0005 Ohm 1% 3W ±175ppm/°C Molded SMD SMD Embossed Plastic T/R; Manufacturer: Vishay Dale; Value: 500µ; TempCo: 150ppm/°C; SizeZ_mm: 0.05inch; AEC Qualified: Yes; AEC Grade: Grade 0
R27 = CMP-0022679-3: RES, 100, 1%, 0.1 W, AEC-Q200 Grade 0, 0603; Manufacturer: Panasonic; Power_W: 100mW; TempCo: 100 ppm/C; Value_Code: 100R; U/M: EA; Value: 100; EIA_Code: E96; SizeX_mm: 1.6; SizeY_mm: 0.8; SizeZ_mm: 1; Value2: 0.1W; SizeArea_mm2: 1.28; AEC Qualified: Y; AEC Grade: 0; AEC Category: Q200
R30 = CMP-0022990-5: RES, 2.49 k, 1%, 0.1 W, 0603; Manufacturer: Yageo; Power_W: 100mW; TempCo: 100 ppm/C; Value_Code: 2k49; Value: 2.49k; EIA_Code: E96; SizeX_mm: 1.6; SizeY_mm: 0.8; SizeZ_mm: 1; Value2: 0.1W; SizeArea_mm2: 1.28; AEC Qualified: N; VDC_V: 75V; AEC Category: Q200; SizeAreaWB_mm2: 4.68
R31 = CMP-0022902-5: RES, 200, 1%, 0.1 W, 0603; Manufacturer: Yageo; Power_W: 100mW; TempCo: 100 ppm/C; Value_Code: 200R; Value: 200; EIA_Code: E96; SizeX_mm: 1.6; SizeY_mm: 0.8; SizeZ_mm: 1; Value2: 0.1W; SizeArea_mm2: 1.28; AEC Qualified: N; VDC_V: 75V; AEC Category: Q200; SizeAreaWB_mm2: 4.68
R33 = CMP-0023007-4: RES, 2.21, 1%, 0.1 W, 0603; Manufacturer: Yageo; Power_W: 100mW; TempCo: 200 ppm/C; Value_Code: 2R21; Value: 2.21; EIA_Code: E96; SizeX_mm: 1.6; SizeY_mm: 0.8; SizeZ_mm: 1; Value2: 0.1W; SizeArea_mm2: 1.28; AEC Qualified: N; VDC_V: 75V; AEC Category: Q200; SizeAreaWB_mm2: 4.68
R34 = CMP-0021863-2: RES, 10.0, 1%, 0.125 W, 0805; Manufacturer: Yageo America; PartNumber: RC0805FR-0710RL; Power_W: 125mW; TempCo: 200 ppm/C; Value_Code: 10R0; U/M: EA; Value: 10.0; EIA_Code: E96; Res_ohm: 10; SizeX_mm: 2; SizeY_mm: 1.25; SizeZ_mm: 1.45; Value2: 0.125W; SizeArea_mm2: 2.5; VDC_V: 150V; AEC Category: Q200
R35 = CMP-0023626-3: RES, 10.0 k, 0.01%, 0.063 W, 0603; Manufacturer: Stackpole Electronics Inc; Power_W: 63mW; TempCo: 5 ppm/C; Value_Code: 10k0; U/M: EA; Value: 10.0k; Res_ohm: 10k; SizeX_mm: 1.6; SizeY_mm: 0.8; SizeZ_mm: 1; Value2: 0.063W; SizeArea_mm2: 1.28; VDC_V: 50V; AEC Category: Q200
R36 = CMP-0023288-5: RES, 820, 1%, 0.1 W, 0603; Manufacturer: Yageo; Power_W: 100mW; TempCo: 100 ppm/C; Value_Code: 820R; Value: 820; SizeX_mm: 1.6; SizeY_mm: 0.8; SizeZ_mm: 1; Value2: 0.1W; SizeArea_mm2: 1.28; AEC Qualified: N; VDC_V: 75V; AEC Category: Q200; SizeAreaWB_mm2: 4.68
R37 = CMP-0023017-5: RES, 309, 1%, 0.1 W, 0603; Manufacturer: Yageo; Power_W: 100mW; TempCo: 100 ppm/C; Value_Code: 309R; Value: 309; EIA_Code: E96; SizeX_mm: 1.6; SizeY_mm: 0.8; SizeZ_mm: 1; Value2: 0.1W; SizeArea_mm2: 1.28; AEC Qualified: N; VDC_V: 75V; AEC Category: Q200; SizeAreaWB_mm2: 4.68
R39 = CMP-0022904-5: as R104 on sheet TPS4HC120-Q1
R40 R41 = CMP-0025686-1: RES, 10.0 k, 0.1%, 0.1 W, AEC-Q200 Grade 1, 0603; Manufacturer: Vishay-Dale; Power_W: 100mW; TempCo: 25 ppm/C; Value_Code: 10k0; U/M: EA; Value: 10.0k; EIA_Code: E192; Res_ohm: 10k; SizeX_mm: 1.6; SizeY_mm: 0.85; SizeZ_mm: 0.55; Value2: 0.1W; SizeArea_mm2: 1.36; AEC Qualified: Y; VDC_V: 75V; AEC Grade: 1; AEC Category: Q200
R42 = CMP-0022449-4: RES, 4.02 k, 1%, 0.1 W, AEC-Q200 Grade 0, 0603; Manufacturer: Vishay-Dale; Power_W: 100mW; TempCo: 100 ppm/C; Value_Code: 4k02; Value: 4.02k; EIA_Code: E96; SizeX_mm: 1.6; SizeY_mm: 0.8; SizeZ_mm: 1; Value2: 0.1W; SizeArea_mm2: 1.28; AEC Qualified: Y; VDC_V: 75V; AEC Category: Q200; AEC Grade: 0
R43 = CMP-0022779-5: RES, 12.0 k, 1%, 0.1 W, 0603; Manufacturer: Yageo; Power_W: 100mW; TempCo: 100 ppm/C; Value_Code: 12k0; Value: 12.0k; Res_ohm: 12k; SizeX_mm: 1.6; SizeY_mm: 0.8; SizeZ_mm: 1; Value2: 0.1W; SizeArea_mm2: 1.28; AEC Qualified: N; VDC_V: 75V; AEC Category: Q200; SizeAreaWB_mm2: 4.68
R44 = CMP-0021990-4: RES, 100 k, 1%, 0.1 W, AEC-Q200 Grade 0, 0603; Manufacturer: Vishay-Dale; Power_W: 100mW; TempCo: 100 ppm/C; Value: 100k; EIA_Code: E96; SizeX_mm: 1.6; SizeY_mm: 0.8; SizeZ_mm: 1; Value2: 0.1W; SizeArea_mm2: 1.28; AEC Qualified: Y; VDC_V: 75V; AEC Category: Q200; AEC Grade: 0
R45 = CMP-0023098-5: RES, 40.2 k, 1%, 0.1 W, 0603; Manufacturer: Yageo; Power_W: 100mW; TempCo: 100 ppm/C; Value_Code: 40k2; Value: 40.2k; EIA_Code: E96; SizeX_mm: 1.6; SizeY_mm: 0.8; SizeZ_mm: 1; Value2: 0.1W; SizeArea_mm2: 1.28; AEC Qualified: N; VDC_V: 75V; AEC Category: Q200; SizeAreaWB_mm2: 4.68
RNTC_1 = CMP-0095715-1: NTC Thermistor for Temperature Sensor, Automotive, 0603, 47kΩ, 5%, 0.046mA, 5V; Manufacturer: Murata; B 25 50: 4050K; B 25 100: 4131K; SizeZ_mm: 0.95mm; AEC Qualified: Yes; B 25 85: 4108K; B Tolerance: 1%; Automotive Grade: Grade 0
TP4-TP7 TP39 TP40 TP55 TP56 = CMP-0055149-1: as TP45 on sheet TPS4HC120-Q1
U3 = CMP-0121394-1: Low IQ Smart High Side gate driver with I2t, Low Power Mode and Diagnostics; Manufacturer: Texas Instruments; SizeZ_mm: 1mm; Standoff Height: 0mm

## Sheet PCB_Project_Hardware.SchDoc
size 431 x 279 mm; Date: Not shown in title block; ApprovedBy: Not shown in title block; CheckedBy: Not shown in title block; Author: Not shown in title block; CompanyName: Not shown in title block; Engineer: Not shown in title block; Organization: Not shown in title block; Address1: Not shown in title block; Address2: Not shown in title block; Address3: Not shown in title block; Address4: Not shown in title block; DocumentNumber: 15; Revision: Use project parameter SCH_Rev; SheetNumber: 15; SheetTotal: 15; PageSetup: Record=PageOptions¦CenterHorizontal=True¦CenterVertical=True¦PrintScale=1.00¦XCorrection=1.00¦YCorrection=1.00¦PrintKind=0¦BorderSize=5000000¦LeftOffset=0¦BottomOffset=0¦Orientation=2¦PaperLength=1000¦PaperWidth=1000¦Scale=100¦PaperSource=15¦PrintQuality=600¦MediaType=1¦DitherType=10¦PaperKind=Letter¦PrintScaleMode=1
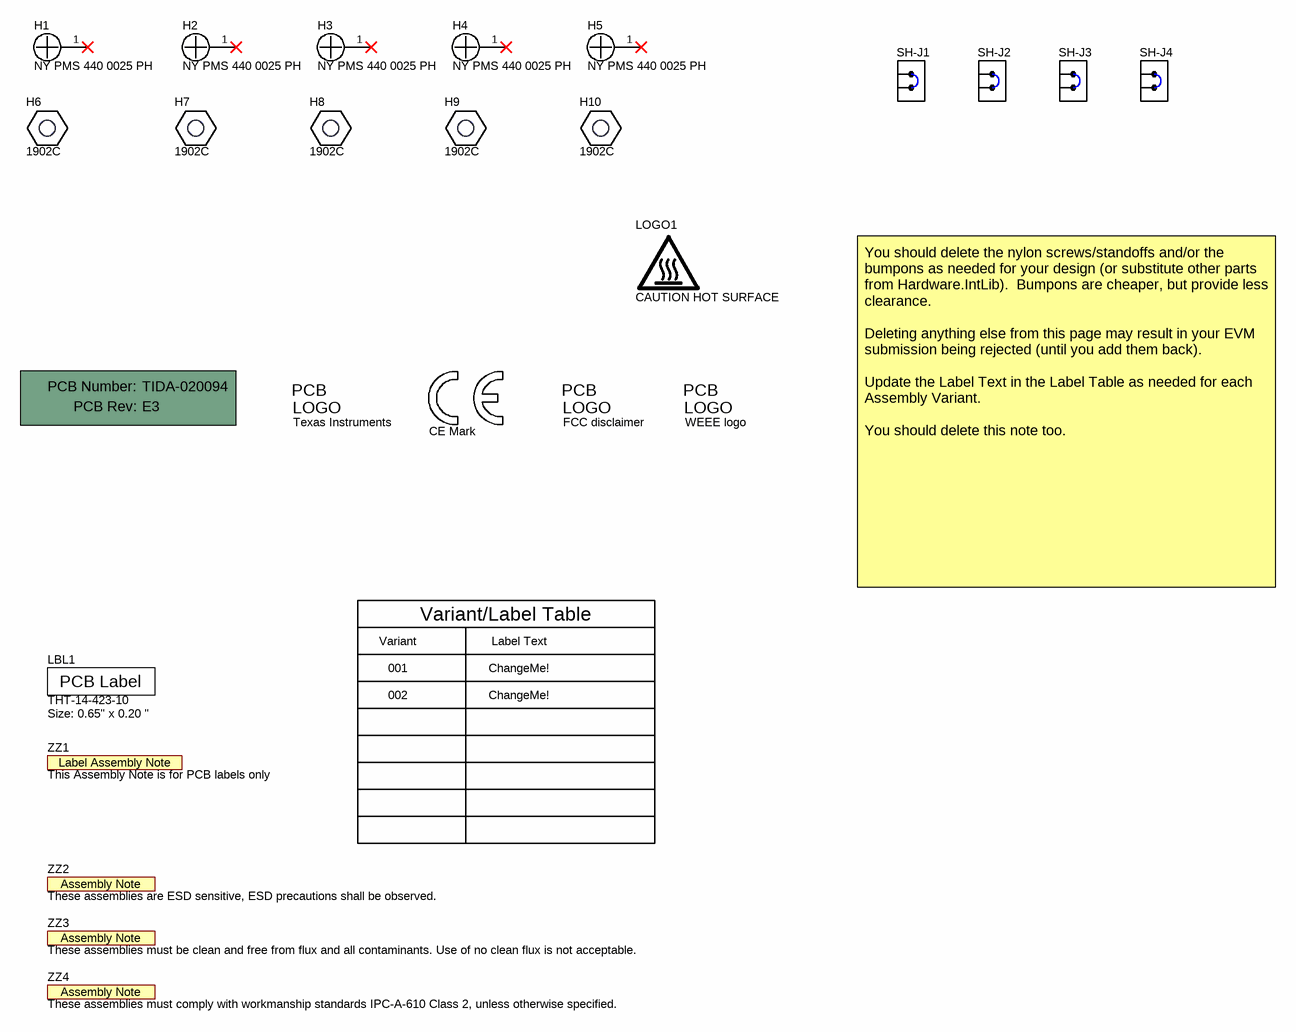
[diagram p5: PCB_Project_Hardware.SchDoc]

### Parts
!PCB1  Printed Circuit Board  (value not drawn)  (mechanical)
H1  NY PMS 440 0025 PH  [NY PMS 440 0025 PH]
H2  NY PMS 440 0025 PH  [NY PMS 440 0025 PH]
H3  NY PMS 440 0025 PH  [NY PMS 440 0025 PH]
H4  NY PMS 440 0025 PH  [NY PMS 440 0025 PH]
H5  NY PMS 440 0025 PH  [NY PMS 440 0025 PH]
H6  1902C  [Keystone_1902C]
H7  1902C  [Keystone_1902C]
H8  1902C  [Keystone_1902C]
H9  1902C  [Keystone_1902C]
H10  1902C  [Keystone_1902C]
LBL1  THT-14-423-10  Note: Size: 0.65" x 0.20 "  [Label_650x200]
LOGO1  CAUTION HOT SURFACE  [IEC_HotSurface_Small]  (no BOM)
Logo2  CE Mark  [CE_Mark_5mm]  (no BOM)
Logo3  Texas Instruments  [TI_Stacked_Overlay_Small]  (no BOM)
Logo4  FCC disclaimer  [FCC_disclaimer]  (no BOM)
Logo5  WEEE logo  [WEEE_Minimum]  (no BOM)
SH-J1  SNT-100-BK-G  [SNT-100-BK-G]  (value not drawn)
SH-J2  SNT-100-BK-G  [SNT-100-BK-G]  (value not drawn)
SH-J3  SNT-100-BK-G  [SNT-100-BK-G]  (value not drawn)
SH-J4  SNT-100-BK-G  [SNT-100-BK-G]  (value not drawn)
ZZ1  This Assembly Note is for PCB labels only  [AssemblyNoteLabel]  (no BOM)
ZZ2  These assemblies are ESD sensitive, ESD precautions shall be observed.  [AssemblyNote]  (no BOM)
ZZ3  These assemblies must be clean and free from flux and all contaminants. Use of no clean flux is not acceptable.  [AssemblyNote]  (no BOM)
ZZ4  These assemblies must comply with workmanship standards IPC-A-610 Class 2, unless otherwise specified.  [AssemblyNote]  (no BOM)

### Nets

Not connected (* = marked no-connect by the designer): H1 1*; H2 1*; H3 1*; H4 1*; H5 1*

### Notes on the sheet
- Variant
- Variant/Label Table
- Label Text
- You should delete the nylon screws/standoffs and/or the bumpons as needed for your design (or substitute other parts from Hardware.IntLib).  Bumpons are cheaper, but provide less clearance.
  Deleting anything else from this page may result in your EVM submission being rejected (until you add them back).
  Update the Label Text in the Label Table as needed for each Assembly Variant.
  You should delete this note too.
- 001
- 002
- ChangeMe!

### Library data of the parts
!PCB1 = CMP-0003618-2: Manufacturer: Any; PartNumber: TIDA-020094
H1-H5 = CMP-0003617-1: Machine Screw, Round, #4-40 x 1/4, Nylon, Philips panhead; Manufacturer: B&F Fastener Supply; CompType: Hardware
H6-H10 = CMP-0003610-1: Standoff, Hex, 0.5"L #4-40 Nylon; Manufacturer: Keystone; CompType: Hardware
LBL1 = CMP-0003625-1: Thermal Transfer Printable Labels, 0.650" W x 0.200" H - 10,000 per roll; Manufacturer: Brady; CompType: Label
LOGO1 = CMP-0074837-1: IEC 61010-1 Hot Surface Warning; SymbolCreator: a0412235
Logo2 = CMP-0074844-1: SymbolCreator: a0412235
Logo3 = CMP-0074838-1: Texas Instrument Corporate Signature; SymbolCreator: a0412235; Lib Reference: TI_Logo; Library Reference: Logo
Logo4 = CMP-0074847-1: FCC_disclaimer; Library Reference: Logo
Logo5 = CMP-0074769-1
SH-J1-SH-J4 = CMP-0003623-3: Shunt, 100mil, Gold plated, Black; Alternate PartNumber: 969102-0000-DA; Manufacturer: Samtec; Alternate Manufacturer: 3M; Value: 1x2
ZZ1 = CMP-0003616-3
ZZ2 = CMP-0077236-1
ZZ3 = CMP-0077237-1
ZZ4 = CMP-0077238-1

## Sheet (BLDC) DRV8363-Q1.SchDoc
size 431 x 279 mm; Date: Not shown in title block; ApprovedBy: Not shown in title block; CheckedBy: Not shown in title block; Author: Not shown in title block; CompanyName: Not shown in title block; Engineer: Not shown in title block; Organization: Not shown in title block; Address1: Not shown in title block; Address2: Not shown in title block; Address3: Not shown in title block; Address4: Not shown in title block; DocumentNumber: 1; Revision: Use project parameter SCH_Rev; SheetNumber: 10; SheetTotal: 15; PageSetup: Record=PageOptions¦CenterHorizontal=True¦CenterVertical=True¦PrintScale=1.00¦XCorrection=1.00¦YCorrection=1.00¦PrintKind=0¦BorderSize=5000000¦LeftOffset=0¦BottomOffset=0¦Orientation=2¦PaperLength=1000¦PaperWidth=1000¦Scale=100¦PaperSource=15¦PrintQuality=600¦MediaType=1¦DitherType=10¦PaperKind=Letter¦PrintScaleMode=1
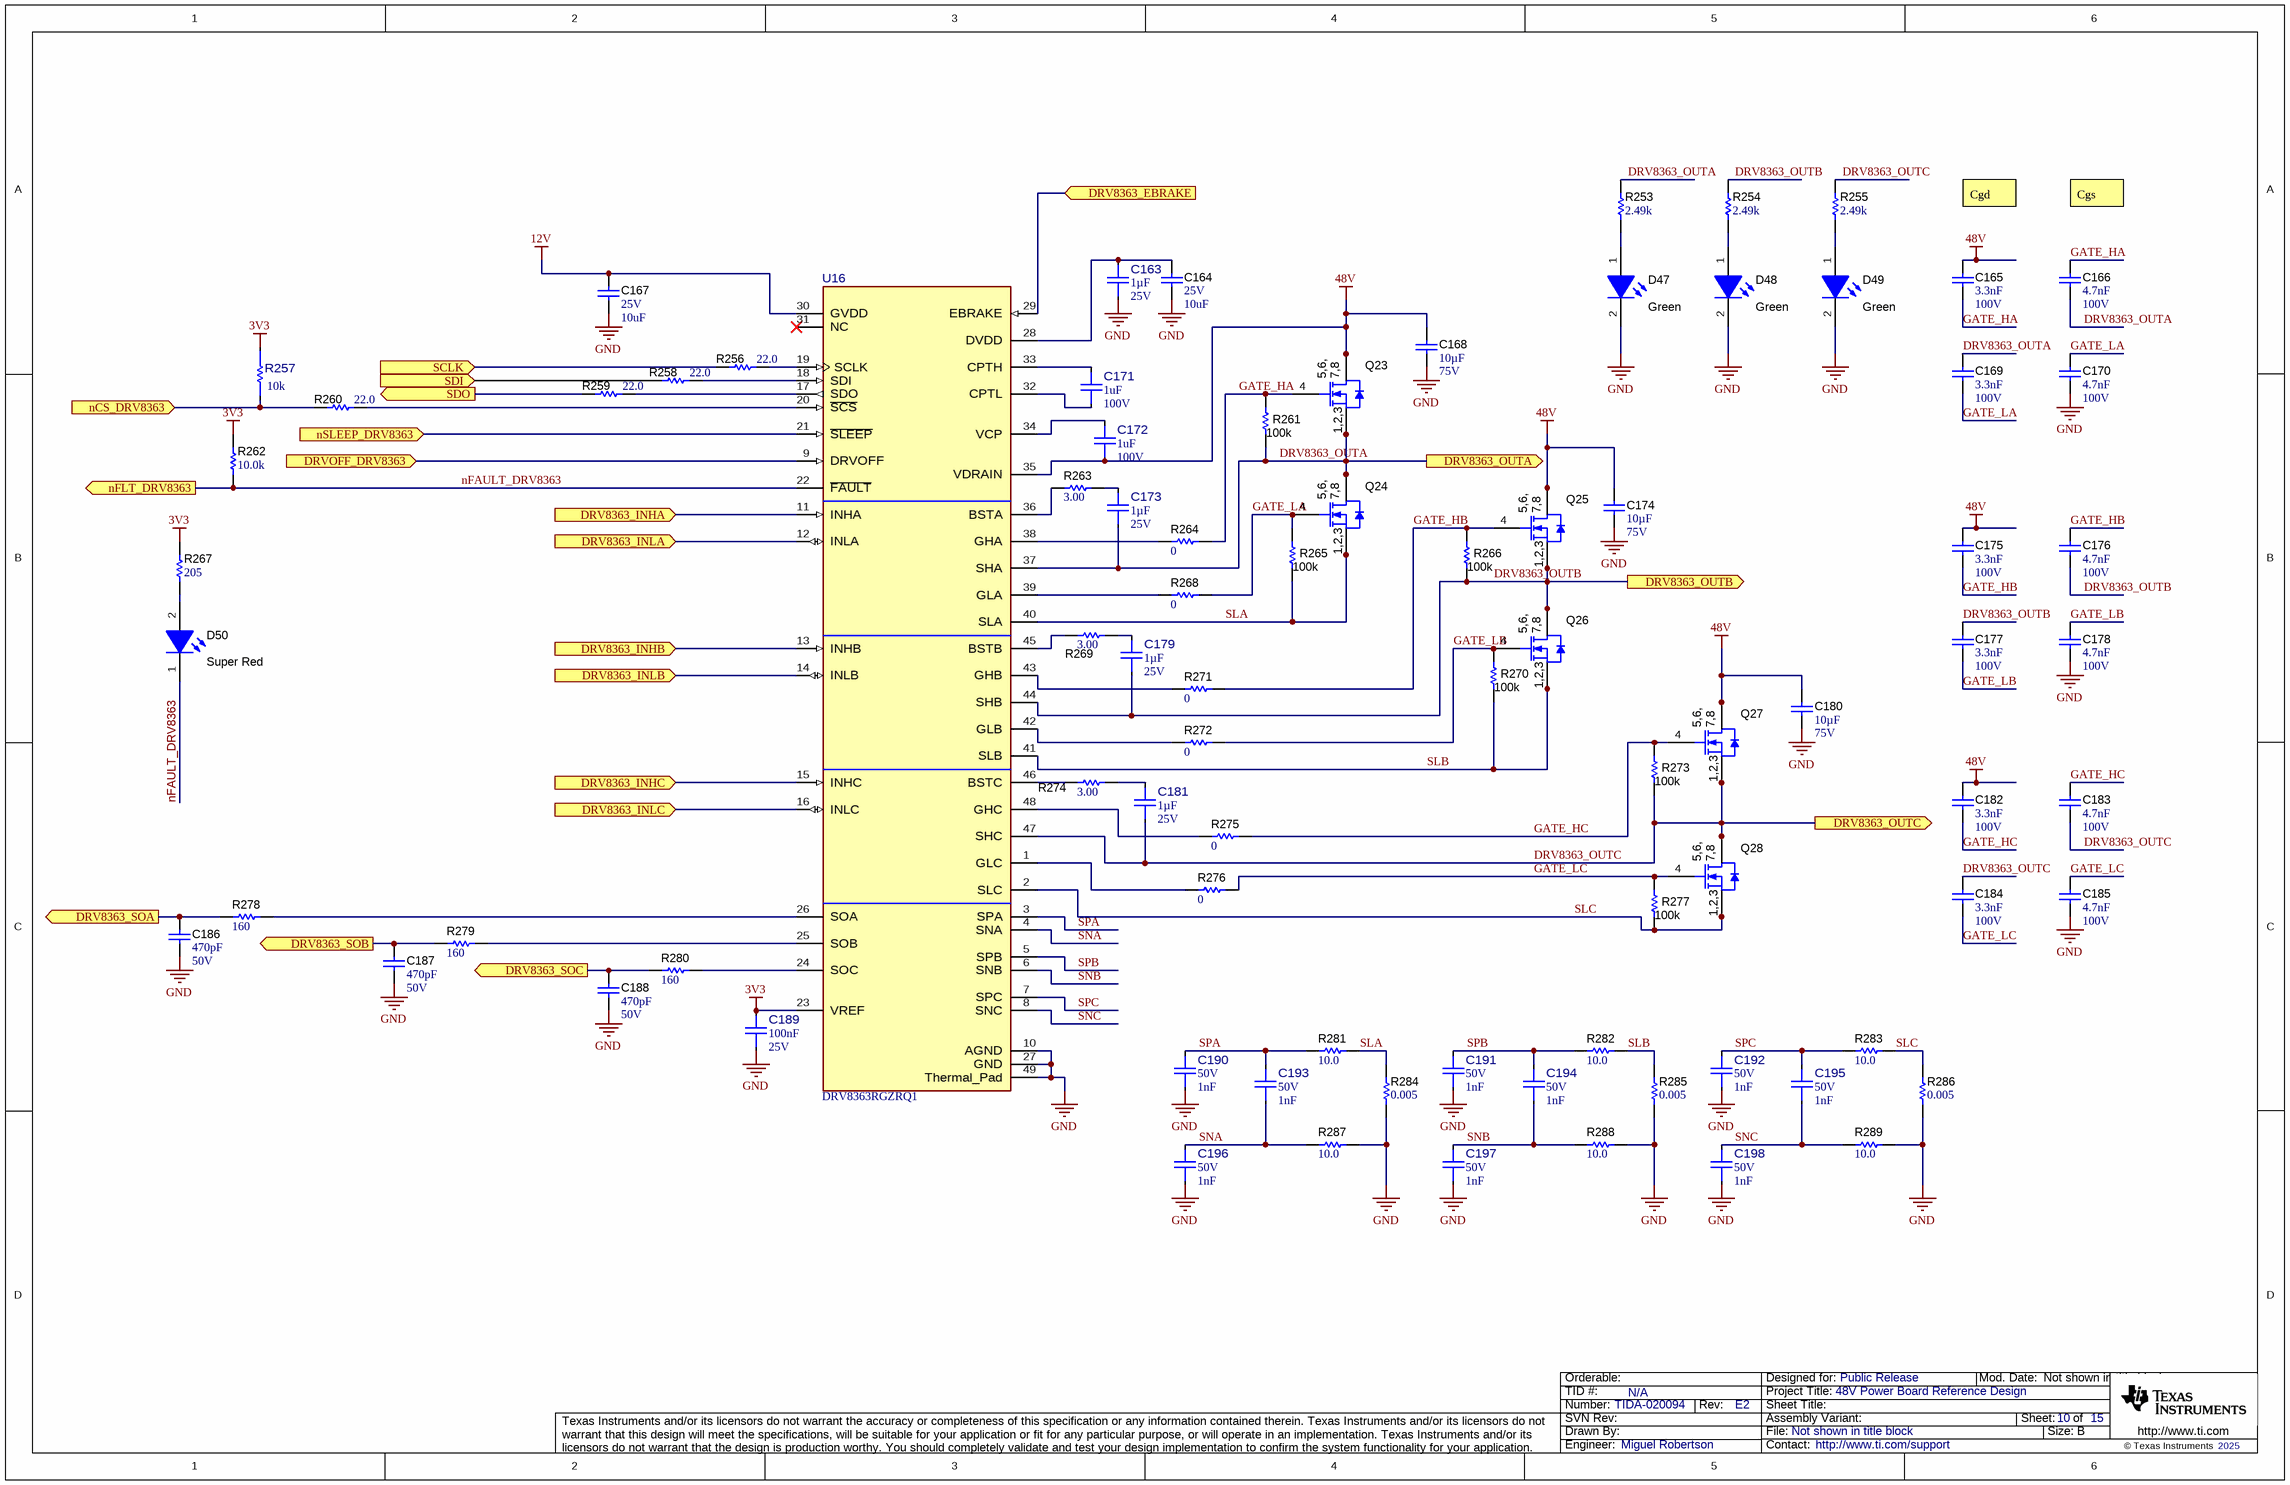
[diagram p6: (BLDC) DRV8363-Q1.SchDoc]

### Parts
C163  Cap_F: 1µF  VDC_V: 25V  [FP-AGC0603X7R250-105KXP_0603-MFG]  (hidden comment: AGC0603X7R250-105KXP)
C164  VDC_V: 25V  ValueDisplayed: 10uF  [0603]  (hidden comment: C1608X5R1E106M080AC)
C165  Cap_F: 3.3nF  VDC_V: 100V  [0603]  (hidden comment: GCM188R72A332KA37D)
C166  Cap_F: 4.7nF  VDC_V: 100V  [0603]  (hidden comment: GCM188R72A472KA37D)
C167  VDC_V: 25V  ValueDisplayed: 10uF  [0603]  (hidden comment: RC0603FR-07200RL)
C168  ValueDisplayed: 10µF  VDC_V: 75V  [1210_280]  (hidden comment: CGA6P1X7R1N106M250AC)
C169  Cap_F: 3.3nF  VDC_V: 100V  [0603]  (hidden comment: GCM188R72A332KA37D)
C170  Cap_F: 4.7nF  VDC_V: 100V  [0603]  (hidden comment: GCM188R72A472KA37D)
C171  ValueDisplayed: 1uF  VDC_V: 100V  [FP-GRM188D72A105KE01D_0603-MFG]  (hidden comment: GRM188D72A105KE01D)
C172  ValueDisplayed: 1uF  VDC_V: 100V  [FP-GRM188D72A105KE01D_0603-MFG]  (hidden comment: GRM188D72A105KE01D)
C173  Cap_F: 1µF  VDC_V: 25V  [FP-CL10B105KA8VPJC_0603-MFG]  (hidden comment: CL10B105KA8VPJC)
C174  ValueDisplayed: 10µF  VDC_V: 75V  [1210_280]  (hidden comment: CGA6P1X7R1N106M250AC)
C175  Cap_F: 3.3nF  VDC_V: 100V  [0603]  (hidden comment: GCM188R72A332KA37D)
C176  Cap_F: 4.7nF  VDC_V: 100V  [0603]  (hidden comment: GCM188R72A472KA37D)
C177  Cap_F: 3.3nF  VDC_V: 100V  [0603]  (hidden comment: GCM188R72A332KA37D)
C178  Cap_F: 4.7nF  VDC_V: 100V  [0603]  (hidden comment: GCM188R72A472KA37D)
C179  Cap_F: 1µF  VDC_V: 25V  [FP-CL10B105KA8VPJC_0603-MFG]  (hidden comment: CL10B105KA8VPJC)
C180  ValueDisplayed: 10µF  VDC_V: 75V  [1210_280]  (hidden comment: CGA6P1X7R1N106M250AC)
C181  Cap_F: 1µF  VDC_V: 25V  [FP-CL10B105KA8VPJC_0603-MFG]  (hidden comment: CL10B105KA8VPJC)
C182  Cap_F: 3.3nF  VDC_V: 100V  [0603]  (hidden comment: GCM188R72A332KA37D)
C183  Cap_F: 4.7nF  VDC_V: 100V  [0603]  (hidden comment: GCM188R72A472KA37D)
C184  Cap_F: 3.3nF  VDC_V: 100V  [0603]  (hidden comment: GCM188R72A332KA37D)
C185  Cap_F: 4.7nF  VDC_V: 100V  [0603]  (hidden comment: GCM188R72A472KA37D)
C186  Cap_F: 470pF  VDC_V: 50V  [0603]  (hidden comment: C0603C471K5RACTU)
C187  Cap_F: 470pF  VDC_V: 50V  [0603]  (hidden comment: C0603C471K5RACTU)
C188  Cap_F: 470pF  VDC_V: 50V  [0603]  (hidden comment: C0603C471K5RACTU)
C189  Cap_F: 100nF  VDC_V: 25V  [FP-CL10B104KA8VPJC_0603-MFG]  (hidden comment: CL10B104KA8VPJC)
C190  VDC_V: 50V  Cap_F: 1nF  [FP-CGA3E2X7R1H102K080AA_0603-MFG]  (hidden comment: CGA3E2X7R1H102K080AA)
C191  VDC_V: 50V  Cap_F: 1nF  [FP-CGA3E2X7R1H102K080AA_0603-MFG]  (hidden comment: CGA3E2X7R1H102K080AA)
C192  VDC_V: 50V  Cap_F: 1nF  [FP-CGA3E2X7R1H102K080AA_0603-MFG]  (hidden comment: CGA3E2X7R1H102K080AA)
C193  VDC_V: 50V  Cap_F: 1nF  [FP-CGA3E2X7R1H102K080AA_0603-MFG]  (hidden comment: CGA3E2X7R1H102K080AA)
C194  VDC_V: 50V  Cap_F: 1nF  [FP-CGA3E2X7R1H102K080AA_0603-MFG]  (hidden comment: CGA3E2X7R1H102K080AA)
C195  VDC_V: 50V  Cap_F: 1nF  [FP-CGA3E2X7R1H102K080AA_0603-MFG]  (hidden comment: CGA3E2X7R1H102K080AA)
C196  VDC_V: 50V  Cap_F: 1nF  [FP-CGA3E2X7R1H102K080AA_0603-MFG]  (hidden comment: CGA3E2X7R1H102K080AA)
C197  VDC_V: 50V  Cap_F: 1nF  [FP-CGA3E2X7R1H102K080AA_0603-MFG]  (hidden comment: CGA3E2X7R1H102K080AA)
C198  VDC_V: 50V  Cap_F: 1nF  [FP-CGA3E2X7R1H102K080AA_0603-MFG]  (hidden comment: CGA3E2X7R1H102K080AA)
D47  value Green  [LTST-C191_Green]  (hidden comment: LTST-C191KGKT)
D48  value Green  [LTST-C191_Green]  (hidden comment: LTST-C191KGKT)
D49  value Green  [LTST-C191_Green]  (hidden comment: LTST-C191KGKT)
D50  value Super Red  [WL-SMCW_RED]  (hidden comment: 150060SS75000)
Q23  CSD19534Q5A  [DQJ0008A]  (value not drawn)
Q24  CSD19534Q5A  [DQJ0008A]  (value not drawn)
Q25  CSD19534Q5A  [DQJ0008A]  (value not drawn)
Q26  CSD19534Q5A  [DQJ0008A]  (value not drawn)
Q27  CSD19534Q5A  [DQJ0008A]  (value not drawn)
Q28  CSD19534Q5A  [DQJ0008A]  (value not drawn)
R253  ValueDisplayed: 2.49k  [0603]  (hidden comment: RC0603FR-072K49L)
R254  ValueDisplayed: 2.49k  [0603]  (hidden comment: RC0603FR-072K49L)
R255  ValueDisplayed: 2.49k  [0603]  (hidden comment: RC0603FR-072K49L)
R256  ValueDisplayed: 22.0  [0201]  (hidden comment: RC0201FR-0722RL)
R257  value 10k  [FP-RC0402JR-0710KL_0402-MFG]  (hidden comment: RC0402JR-0710KL)
R258  ValueDisplayed: 22.0  [0201]  (hidden comment: RC0201FR-0722RL)
R259  ValueDisplayed: 22.0  [0201]  (hidden comment: RC0201FR-0722RL)
R260  ValueDisplayed: 22.0  [0201]  (hidden comment: RC0201FR-0722RL)
R261  ValueDisplayed: 100k  [0603L]  (hidden comment: CRCW0603100KFKEA)
R262  ValueDisplayed: 10.0k  [TNPW0603]  (hidden comment: TNPW060310K0BEEA)
R263  ValueDisplayed: 3.00  [0603]  (hidden comment: KTR03EZPF3R00)
R264  ValueDisplayed: 0  [0603]  (hidden comment: ERJ-3GEY0R00V)
R265  ValueDisplayed: 100k  [0603L]  (hidden comment: CRCW0603100KFKEA)
R266  ValueDisplayed: 100k  [0603L]  (hidden comment: CRCW0603100KFKEA)
R267  ValueDisplayed: 205  [0603]  (hidden comment: RC0603FR-07205RL)
R268  ValueDisplayed: 0  [0603]  (hidden comment: ERJ-3GEY0R00V)
R269  ValueDisplayed: 3.00  [0603]  (hidden comment: KTR03EZPF3R00)
R270  ValueDisplayed: 100k  [0603L]  (hidden comment: CRCW0603100KFKEA)
R271  ValueDisplayed: 0  [0603]  (hidden comment: ERJ-3GEY0R00V)
R272  ValueDisplayed: 0  [0603]  (hidden comment: ERJ-3GEY0R00V)
R273  ValueDisplayed: 100k  [0603L]  (hidden comment: CRCW0603100KFKEA)
R274  ValueDisplayed: 3.00  [0603]  (hidden comment: KTR03EZPF3R00)
R275  ValueDisplayed: 0  [0603]  (hidden comment: ERJ-3GEY0R00V)
R276  ValueDisplayed: 0  [0603]  (hidden comment: ERJ-3GEY0R00V)
R277  ValueDisplayed: 100k  [0603L]  (hidden comment: CRCW0603100KFKEA)
R278  ValueDisplayed: 160  [0603]  (hidden comment: RC0603FR-07160RL)
R279  ValueDisplayed: 160  [0603]  (hidden comment: RC0603FR-07160RL)
R280  ValueDisplayed: 160  [0603]  (hidden comment: RC0603FR-07160RL)
R281  ValueDisplayed: 10.0  [0603]  (hidden comment: RC0603FR-0710RL)
R282  ValueDisplayed: 10.0  [0603]  (hidden comment: RC0603FR-0710RL)
R283  ValueDisplayed: 10.0  [0603]  (hidden comment: RC0603FR-0710RL)
R284  ValueDisplayed: 0.005  [CRE2512-R5_R9]  (hidden comment: CRE2512-FZ-R005E-3)
R285  ValueDisplayed: 0.005  [CRE2512-R5_R9]  (hidden comment: CRE2512-FZ-R005E-3)
R286  ValueDisplayed: 0.005  [CRE2512-R5_R9]  (hidden comment: CRE2512-FZ-R005E-3)
R287  ValueDisplayed: 10.0  [0603]  (hidden comment: RC0603FR-0710RL)
R288  ValueDisplayed: 10.0  [0603]  (hidden comment: RC0603FR-0710RL)
R289  ValueDisplayed: 10.0  [0603]  (hidden comment: RC0603FR-0710RL)
U16  DRV8363RGZRQ1  [RGZ0048L-MFG]

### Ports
DRV8363_EBRAKE (in), DRV8363_INHA (in), DRV8363_INHB (in), DRV8363_INHC (in), DRV8363_INLA (in), DRV8363_INLB (in), DRV8363_INLC (in), DRV8363_OUTA (out), DRV8363_OUTB (out), DRV8363_OUTC (out), DRV8363_SOA (out), DRV8363_SOB (out), DRV8363_SOC (out), DRVOFF_DRV8363 (in), nCS_DRV8363 (in), nFLT_DRV8363 (out), nSLEEP_DRV8363 (in), SCLK (in), SDI (in), SDO (out)

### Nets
3V3: C189.2 R257.1 R262.2 R267.2 U16.23(VREF)
12V: C167.1 U16.30(GVDD)
48V: C165.1 C168.1 C172.1 C174.1 C175.1 C180.1 C182.1 Q23.5(D) Q23.6(D) Q23.7(D) Q23.8(D) Q23.9(D) Q25.5(D) Q25.6(D) Q25.7(D) Q25.8(D) Q25.9(D) Q27.5(D) Q27.6(D) Q27.7(D) Q27.8(D) Q27.9(D) U16.35(VDRAIN)
GND: C163.1 C164.2 C167.2 C168.2 C170.2 C174.2 C178.2 C180.2 C185.2 C186.2 C187.2 C188.2 C189.1 C190.1 C191.1 C192.1 C196.1 C197.1 C198.1 D47.2(K) D48.2(K) D49.2(K) R284.1 R285.1 R286.1 R287.2 R288.2 R289.2 U16.10(AGND) U16.27(GND) U16.49(Thermal_Pad)
: R258.1 ; port SDI
DRV8363_EBRAKE: U16.29(EBRAKE) ; port DRV8363_EBRAKE
DRV8363_INHA: U16.11(INHA) ; port DRV8363_INHA
DRV8363_INHB: U16.13(INHB) ; port DRV8363_INHB
DRV8363_INHC: U16.15(INHC) ; port DRV8363_INHC
DRV8363_INLA: U16.12(INLA) ; port DRV8363_INLA
DRV8363_INLB: U16.14(INLB) ; port DRV8363_INLB
DRV8363_INLC: U16.16(INLC) ; port DRV8363_INLC
DRV8363_OUTA: C166.2 C169.1 C173.1 Q23.1(S) Q23.2(S) Q23.3(S) Q24.5(D) Q24.6(D) Q24.7(D) Q24.8(D) Q24.9(D) R253.2 R261.2 U16.37(SHA) ; port DRV8363_OUTA
DRV8363_OUTB: C176.2 C177.1 C179.1 Q25.1(S) Q25.2(S) Q25.3(S) Q26.5(D) Q26.6(D) Q26.7(D) Q26.8(D) Q26.9(D) R254.2 R266.2 U16.44(SHB) ; port DRV8363_OUTB
DRV8363_OUTC: C181.1 C183.2 C184.1 Q27.1(S) Q27.2(S) Q27.3(S) Q28.5(D) Q28.6(D) Q28.7(D) Q28.8(D) Q28.9(D) R255.2 R273.2 U16.47(SHC) ; port DRV8363_OUTC
DRV8363_SOA: C186.1 R278.1 ; port DRV8363_SOA
DRV8363_SOB: C187.1 R279.1 ; port DRV8363_SOB
DRV8363_SOC: C188.1 R280.1 ; port DRV8363_SOC
DRVOFF_DRV8363: U16.9(DRVOFF) ; port DRVOFF_DRV8363
GATE_HA: C165.2 C166.1 Q23.4(G) R261.1 R264.1  [project net GATE_HA_10]
GATE_HB: C175.2 C176.1 Q25.4(G) R266.1 R271.1  [project net GATE_HB_10]
GATE_HC: C182.2 C183.1 Q27.4(G) R273.1 R275.1  [project net GATE_HC_10]
GATE_LA: C169.2 C170.1 Q24.4(G) R265.1 R268.1  [project net GATE_LA_10]
GATE_LB: C177.2 C178.1 Q26.4(G) R270.1 R272.1  [project net GATE_LB_10]
GATE_LC: C184.2 C185.1 Q28.4(G) R276.1 R277.1  [project net GATE_LC_10]
nCS_DRV8363: R257.2 R260.1 ; port nCS_DRV8363
nFAULT_DRV8363: D50.1(K) R262.1 U16.22(~{FAULT}) ; port nFLT_DRV8363
nSLEEP_DRV8363: U16.21(~{SLEEP}) ; port nSLEEP_DRV8363
SCLK: R256.1 ; port SCLK
SDO: R259.1 ; port SDO
SLA: Q24.1(S) Q24.2(S) Q24.3(S) R265.2 R281.2 R284.2 U16.40(SLA)  [project net SLA_10]
SLB: Q26.1(S) Q26.2(S) Q26.3(S) R270.2 R282.2 R285.2 U16.41(SLB)  [project net SLB_10]
SLC: Q28.1(S) Q28.2(S) Q28.3(S) R277.2 R283.2 R286.2 U16.2(SLC)  [project net SLC_10]
SNA: C193.1 C196.2 R287.1 U16.4(SNA)  [project net SNA_10]
SNB: C194.1 C197.2 R288.1 U16.6(SNB)  [project net SNB_10]
SNC: C195.1 C198.2 R289.1 U16.8(SNC)  [project net SNC_10]
SPA: C190.2 C193.2 R281.1 U16.3(SPA)  [project net SPA_10]
SPB: C191.2 C194.2 R282.1 U16.5(SPB)  [project net SPB_10]
SPC: C192.2 C195.2 R283.1 U16.7(SPC)  [project net SPC_10]
NetC163_2: C163.2 C164.1 U16.28(DVDD)
NetC171_1: C171.1 U16.32(CPTL)
NetC171_2: C171.2 U16.33(CPTH)
NetC172_2: C172.2 U16.34(VCP)
NetC173_2: C173.2 R263.2
NetC179_2: C179.2 R269.2
NetC181_2: C181.2 R274.2
NetD47_1: D47.1(A) R253.1
NetD48_1: D48.1(A) R254.1
NetD49_1: D49.1(A) R255.1
NetD50_2: D50.2(A) R267.1
NetR256_2: R256.2 U16.19(SCLK)
NetR258_2: R258.2 U16.18(SDI)
NetR259_2: R259.2 U16.17(SDO)
NetR260_2: R260.2 U16.20(~{SCS})
NetR263_1: R263.1 U16.36(BSTA)
NetR264_2: R264.2 U16.38(GHA)
NetR268_2: R268.2 U16.39(GLA)
NetR269_1: R269.1 U16.45(BSTB)
NetR271_2: R271.2 U16.43(GHB)
NetR272_2: R272.2 U16.42(GLB)
NetR274_1: R274.1 U16.46(BSTC)
NetR275_2: R275.2 U16.48(GHC)
NetR276_2: R276.2 U16.1(GLC)
NetR278_2: R278.2 U16.26(SOA)
NetR279_2: R279.2 U16.25(SOB)
NetR280_2: R280.2 U16.24(SOC)

Not connected (* = marked no-connect by the designer): U16 31(NC)*

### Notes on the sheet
- Cgd
- Cgs

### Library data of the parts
C163 = CMP-0123897-1: Auto Grade Capacitor, 0603, X7R, 25V, 1uF, ±10%; Manufacturer: Venkel; AEC Grade: Grade 1; AEC Qualified: Yes; SizeZ_mm: 0.95mm; TempCo: 15%; Value: 1µF
C164 = CMP-0007007-3: CAP, CERM, 10 uF, 25 V, +/- 20%, X5R, 0603; Manufacturer: TDK; TaMin_C: -55°C; ESR_ohm: 4.639m; Polarized: N; SizeAreaWB_mm2: 4.68; Value1: 0.004639 ohm; U/M: EA; Value: 10uF; TaMax_C: 85°C; SizeZ_mm: 1; SizeX_mm: 1.6; SizeY_mm: 0.8; SizeArea_mm2: 1.28; Cap_F: 10µF; IRMS_A: 2.4141A; AEC Category: Q200
C165 C169 C175 C177 C182 C184 = CMP-0007148-4: CAP, CERM, 3300 pF, 100 V, +/- 10%, X7R, AEC-Q200 Grade 1, 0603; Manufacturer: MuRata; TaMin_C: -55°C; Polarized: N; SizeAreaWB_mm2: 4.68; Value1: Unknown; U/M: EA; Value: 3300pF; TaMax_C: 125°C; SizeZ_mm: 1; SizeX_mm: 1.6; SizeY_mm: 0.8; SizeArea_mm2: 1.28; AEC Qualified: Y; AEC Category: Q200
C166 C170 C176 C178 C183 C185 = CMP-0079247-1: CAP, CERM, 4700 pF, 100 V,+/- 10%, X7R, AEC-Q200 Grade 1, 0603; Manufacturer: MuRata; SizeAreaWB_mm2: 4.68; SizeArea_mm2: 1.28; AEC Qualified: Y; AEC Category: Q200; Value: 4700pF; TaMax_C: 125°C; SizeZ_mm: 1; Polarized: N; TaMin_C: -55°C; SizeY_mm: 0.8; U/M: EA; SizeX_mm: 1.6
C167 = CMP-0007007-3: CAP, CERM, 10 uF, 25 V, +/- 20%, X5R, 0603; Manufacturer: TDK; PartNumber: C1608X5R1E106M080AC; TaMin_C: -55°C; ESR_ohm: 4.639m; Polarized: N; SizeAreaWB_mm2: 4.68; Value1: 0.004639 ohm; U/M: EA; Value: 10uF; TaMax_C: 85°C; SizeZ_mm: 1; SizeX_mm: 1.6; SizeY_mm: 0.8; SizeArea_mm2: 1.28; Cap_F: 10µF; IRMS_A: 2.4141A; AEC Category: Q200
C168 C174 C180 = CMP-0085951-1: CAP, CERM, 10 µF, 75 V,+/- 20%, X7R, AEC-Q200 Grade 1, 1210; Manufacturer: TDK; SizeX_mm: 3.2; Cap_Case: 1210; AEC Qualified: Y; Polarized: N; AEC Category: Q200; U/M: EA; SizeZ_mm: 2.8; SizeY_mm: 2.5; TaMin_C: -55°C; AEC Grade: 1; SizeAreaWB_mm2: 14.7; SizeArea_mm2: 8; TaMax_C: 125°C; Value: 10uF
C171 C172 = CMP-0125363-1: 1 µF ±10% 100V Ceramic Capacitor X7T 0603 (1608 Metric); Manufacturer: Murata; AEC Qualified: No; Cap_F: 1µF; SizeZ_mm: 1mm; TempCo: +22/-33%; Value: 1µF
C173 C179 C181 = CMP-0121052-1: Cap Ceramic 1uF 25V X7R ±10% Pad SMD 0603 +125°C T/R; Manufacturer: Samsung; AEC Grade: Grade 1; AEC Qualified: Yes; SizeZ_mm: 0.9mm; TempCo: 15%; Value: 1µF
C186-C188 = CMP-0006940-4: CAP, CERM, 470 pF, 50 V, +/- 10%, X7R, 0603; Manufacturer: Kemet; TaMin_C: -55°C; Polarized: N; SizeAreaWB_mm2: 4.68; Value1: Unknown; U/M: EA; Value: 470pF; TaMax_C: 125°C; SizeZ_mm: 1; SizeX_mm: 1.6; SizeY_mm: 0.8; SizeArea_mm2: 1.28; AEC Category: Q200
C189 = CMP-0121051-1: Automotive CAP, 100㎋, 25V, ±10%, X7R, 0603, 5mm Bending; Manufacturer: Samsung; AEC Grade: Grade 1; AEC Qualified: Yes; SizeZ_mm: 0.9mm; TempCo: 15%; Value: 100nF
C190-C198 = CMP-0094874-1: Cap Ceramic 1nF 50V X7R 10% Pad SMD 0603 +125°C Automotive T/R; Manufacturer: TDK; Tolerance_%: 0.1%; AEC Qualified: Yes; SizeZ_mm: 1.1mm; AEC Grade: Grade 1; TempCo: 0.15
D47-D49 = CMP-0078478-1: as D20-D23 on sheet TPS4HC120-Q1
D50 = CMP-0002893-1: as D19 on sheet TPS4HC120-Q1
Q23-Q28 = CMP-0000962-2: MOSFET, N-CH, 100 V, 10 A, DQJ0008A (VSONP-8); Alternate Manufacturer: None; Manufacturer: Texas Instruments; SizeZ_mm: 1.1; ChType: N; Value2: 17 nC; VdsMax_V: 100V; SizeX_mm: 6; SizeAreaWB_mm2: 55.2; SizeY_mm: 4.9; Vgs_V: 20V; QgTyp_nC: 17; Value: 100V; SizeArea_mm2: 29.4; AEC Category: Q101; IdsMax_A: 10A; U/M: EA
R253-R255 = CMP-0022990-5: as R30 on sheet TPS1214-Q1
R256 R258-R260 = CMP-0027500-1: RES, 22.0, 1%, 0.05 W, 0201; Manufacturer: Yageo America; Power_W: 50mW; TempCo: 200 ppm/C; Value_Code: 22R0; U/M: EA; Value: 22.0; Res_ohm: 22; SizeX_mm: 0.6; SizeY_mm: 0.3; SizeZ_mm: 0.26; Value2: 0.05W; SizeArea_mm2: 0.18; AEC Qualified: N; VDC_V: 25V; AEC Category: Q200
R257 = CMP-0094798-1: Res Thick Film 0402 10K Ohm 5% 0.063W(1/16W) ±100ppm/C Pad SMD T/R; Manufacturer: YAGEO; AEC Qualified: No; Category Cd01000Bfc2916C6: Single Components; SizeZ_mm: 0.4mm; VDC_V: 50V; Category 5C6A91606D4187Ad: Resistors; TempCo: 100ppm/°C; Power_W: 63mW; Category 7542B8484461Ae85: Passive Components
R261 R265 R266 R270 R273 R277 = CMP-0021990-4: as R44 on sheet TPS1214-Q1
R262 = CMP-0025686-1: as R40 on sheet TPS1214-Q1
R263 R269 R274 = CMP-0078498-1: RES, 3.00, 1%, 0.1 W, AEC-Q200 Grade 0, 0603; Manufacturer: Rohm; Power_W: 100mW; TempCo: 100 ppm/C; Value_Code: 3R00; Value: 3.00; Res_ohm: 3; SizeX_mm: 1.6; SizeY_mm: 0.8; SizeZ_mm: 1; Value2: 0.1W; SizeArea_mm2: 1.28; AEC Qualified: Y; VDC_V: 350V; AEC Grade: 0; AEC Category: Q200
R264 R268 R271 R272 R275 R276 = CMP-0025874-4: RES, 0, 5%, 0.1 W, AEC-Q200 Grade 0, 0603; Manufacturer: Panasonic; Power_W: 100mW; TempCo: 600 ppm/C; Value_Code: 0000; Value: 0; EIA_Code: E24; SizeX_mm: 1.6; SizeY_mm: 0.8; SizeZ_mm: 1; Value2: 0.1W; SizeArea_mm2: 1.28; AEC Qualified: Y; VDC_V: 50V; AEC Category: Q200; SizeAreaWB_mm2: 4.68
R267 = CMP-0022904-5: as R104 on sheet TPS4HC120-Q1
R278-R280 = CMP-0022821-5: RES, 160, 1%, 0.1 W, 0603; Manufacturer: Yageo; Power_W: 100mW; TempCo: 100 ppm/C; Value_Code: 160R; Value: 160; SizeX_mm: 1.6; SizeY_mm: 0.8; SizeZ_mm: 1; Value2: 0.1W; SizeArea_mm2: 1.28; AEC Qualified: N; VDC_V: 75V; AEC Category: Q200; SizeAreaWB_mm2: 4.68
R281-R283 R287-R289 = CMP-0022751-4: as R307 on sheet TPS4HC120-Q1
R284-R286 = CMP-0015751-2: RES, 0.005, 1%, 3 W, AEC-Q200 Grade 0, 2512; Manufacturer: Bourns; Power_W: 3W; TempCo: 75 ppm/C; Value_Code: 5L000; U/M: EA; Value: 0.005; EIA_Code: E96; Res_ohm: 5m; SizeX_mm: 6.45; SizeY_mm: 3.35; SizeZ_mm: 0.9; SizeArea_mm2: 21.6075; AEC Qualified: Y; AEC Grade: 0; AEC Category: Q200
U16 = CMP-0122985-1: 48V Battery Three-Phase Smart Gate Driver with Accurate Current Sensing and Advanced Monitoring; Manufacturer: Texas Instruments; SizeZ_mm: 1mm; AEC Qualified: Yes; AEC Grade: Grade 1; Max Supply Voltage: 85V; Min Supply Voltage: 8V; Number Of Drivers: 3; Propagation Delay: 42ns; Standoff Height: 0mm; TaMax_C: +125°C; TaMin_C: -40°C; TJmax_C: +150°C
